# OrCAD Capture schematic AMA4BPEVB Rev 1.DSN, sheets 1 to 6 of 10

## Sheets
1 P03: Power Supplies: size Custom; title: AMA4BPEVB; rev: 1; note: AMSCH-0088
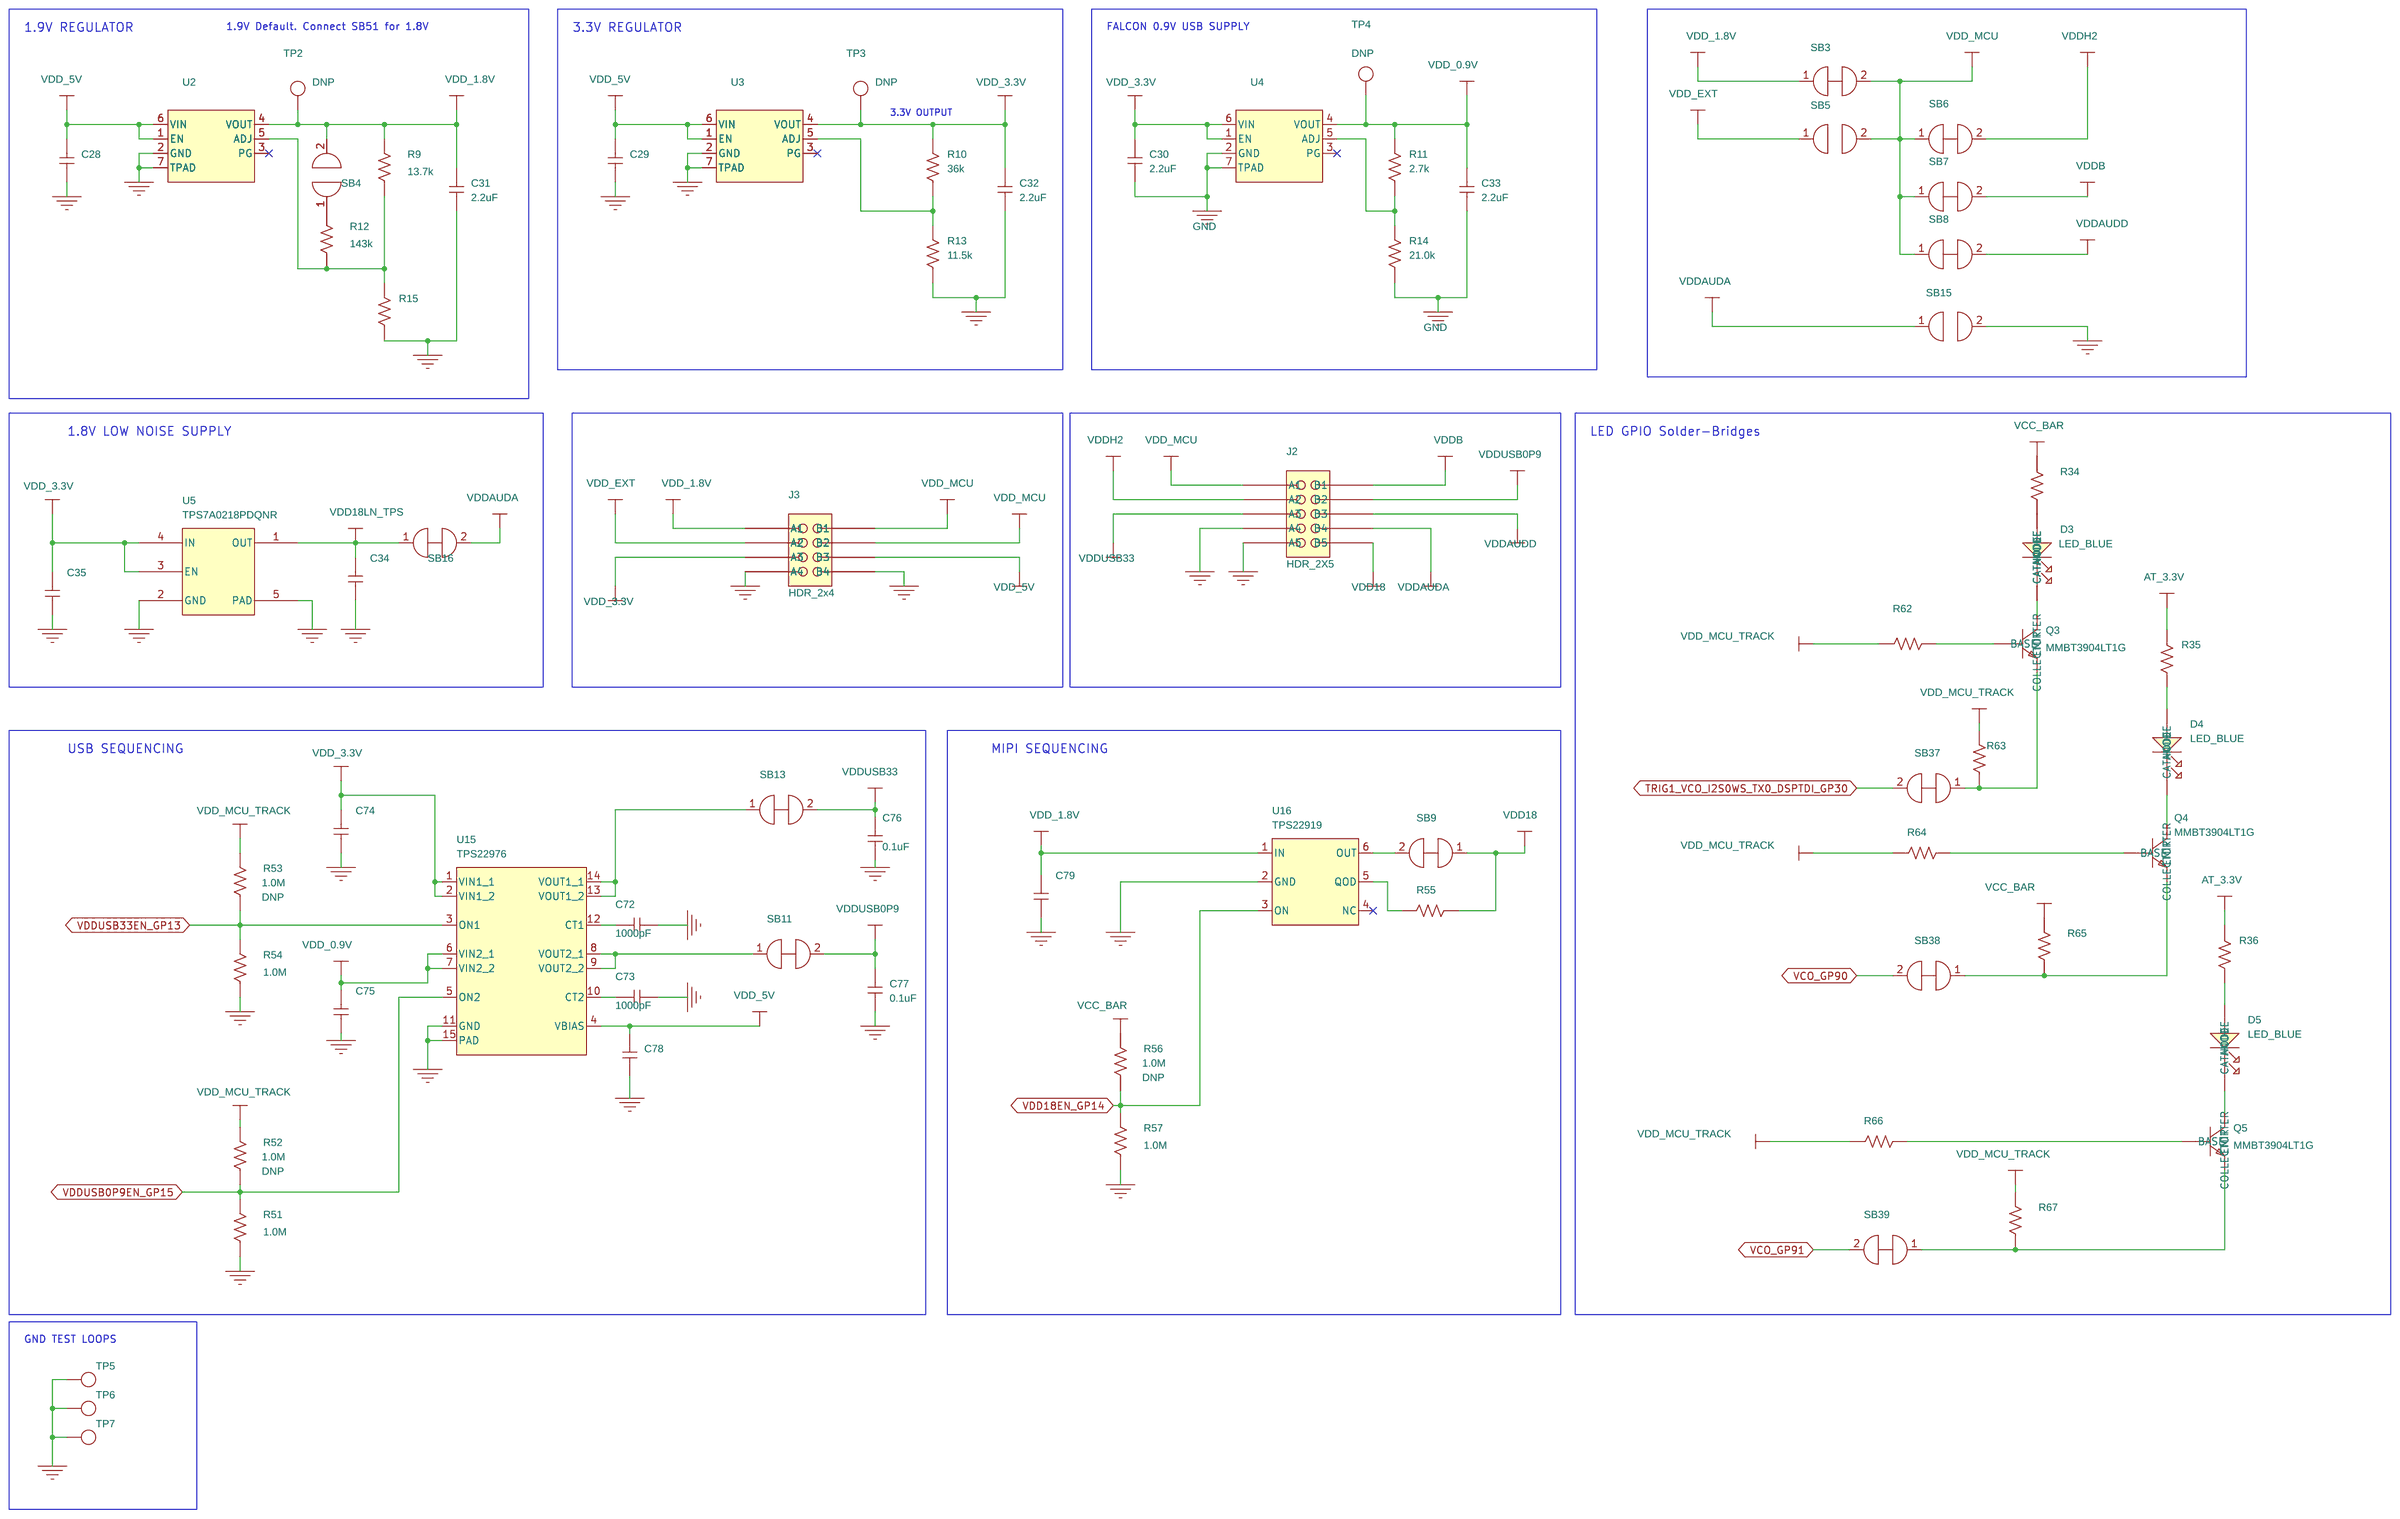
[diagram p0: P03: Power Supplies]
2 P05: Debugger: size Custom
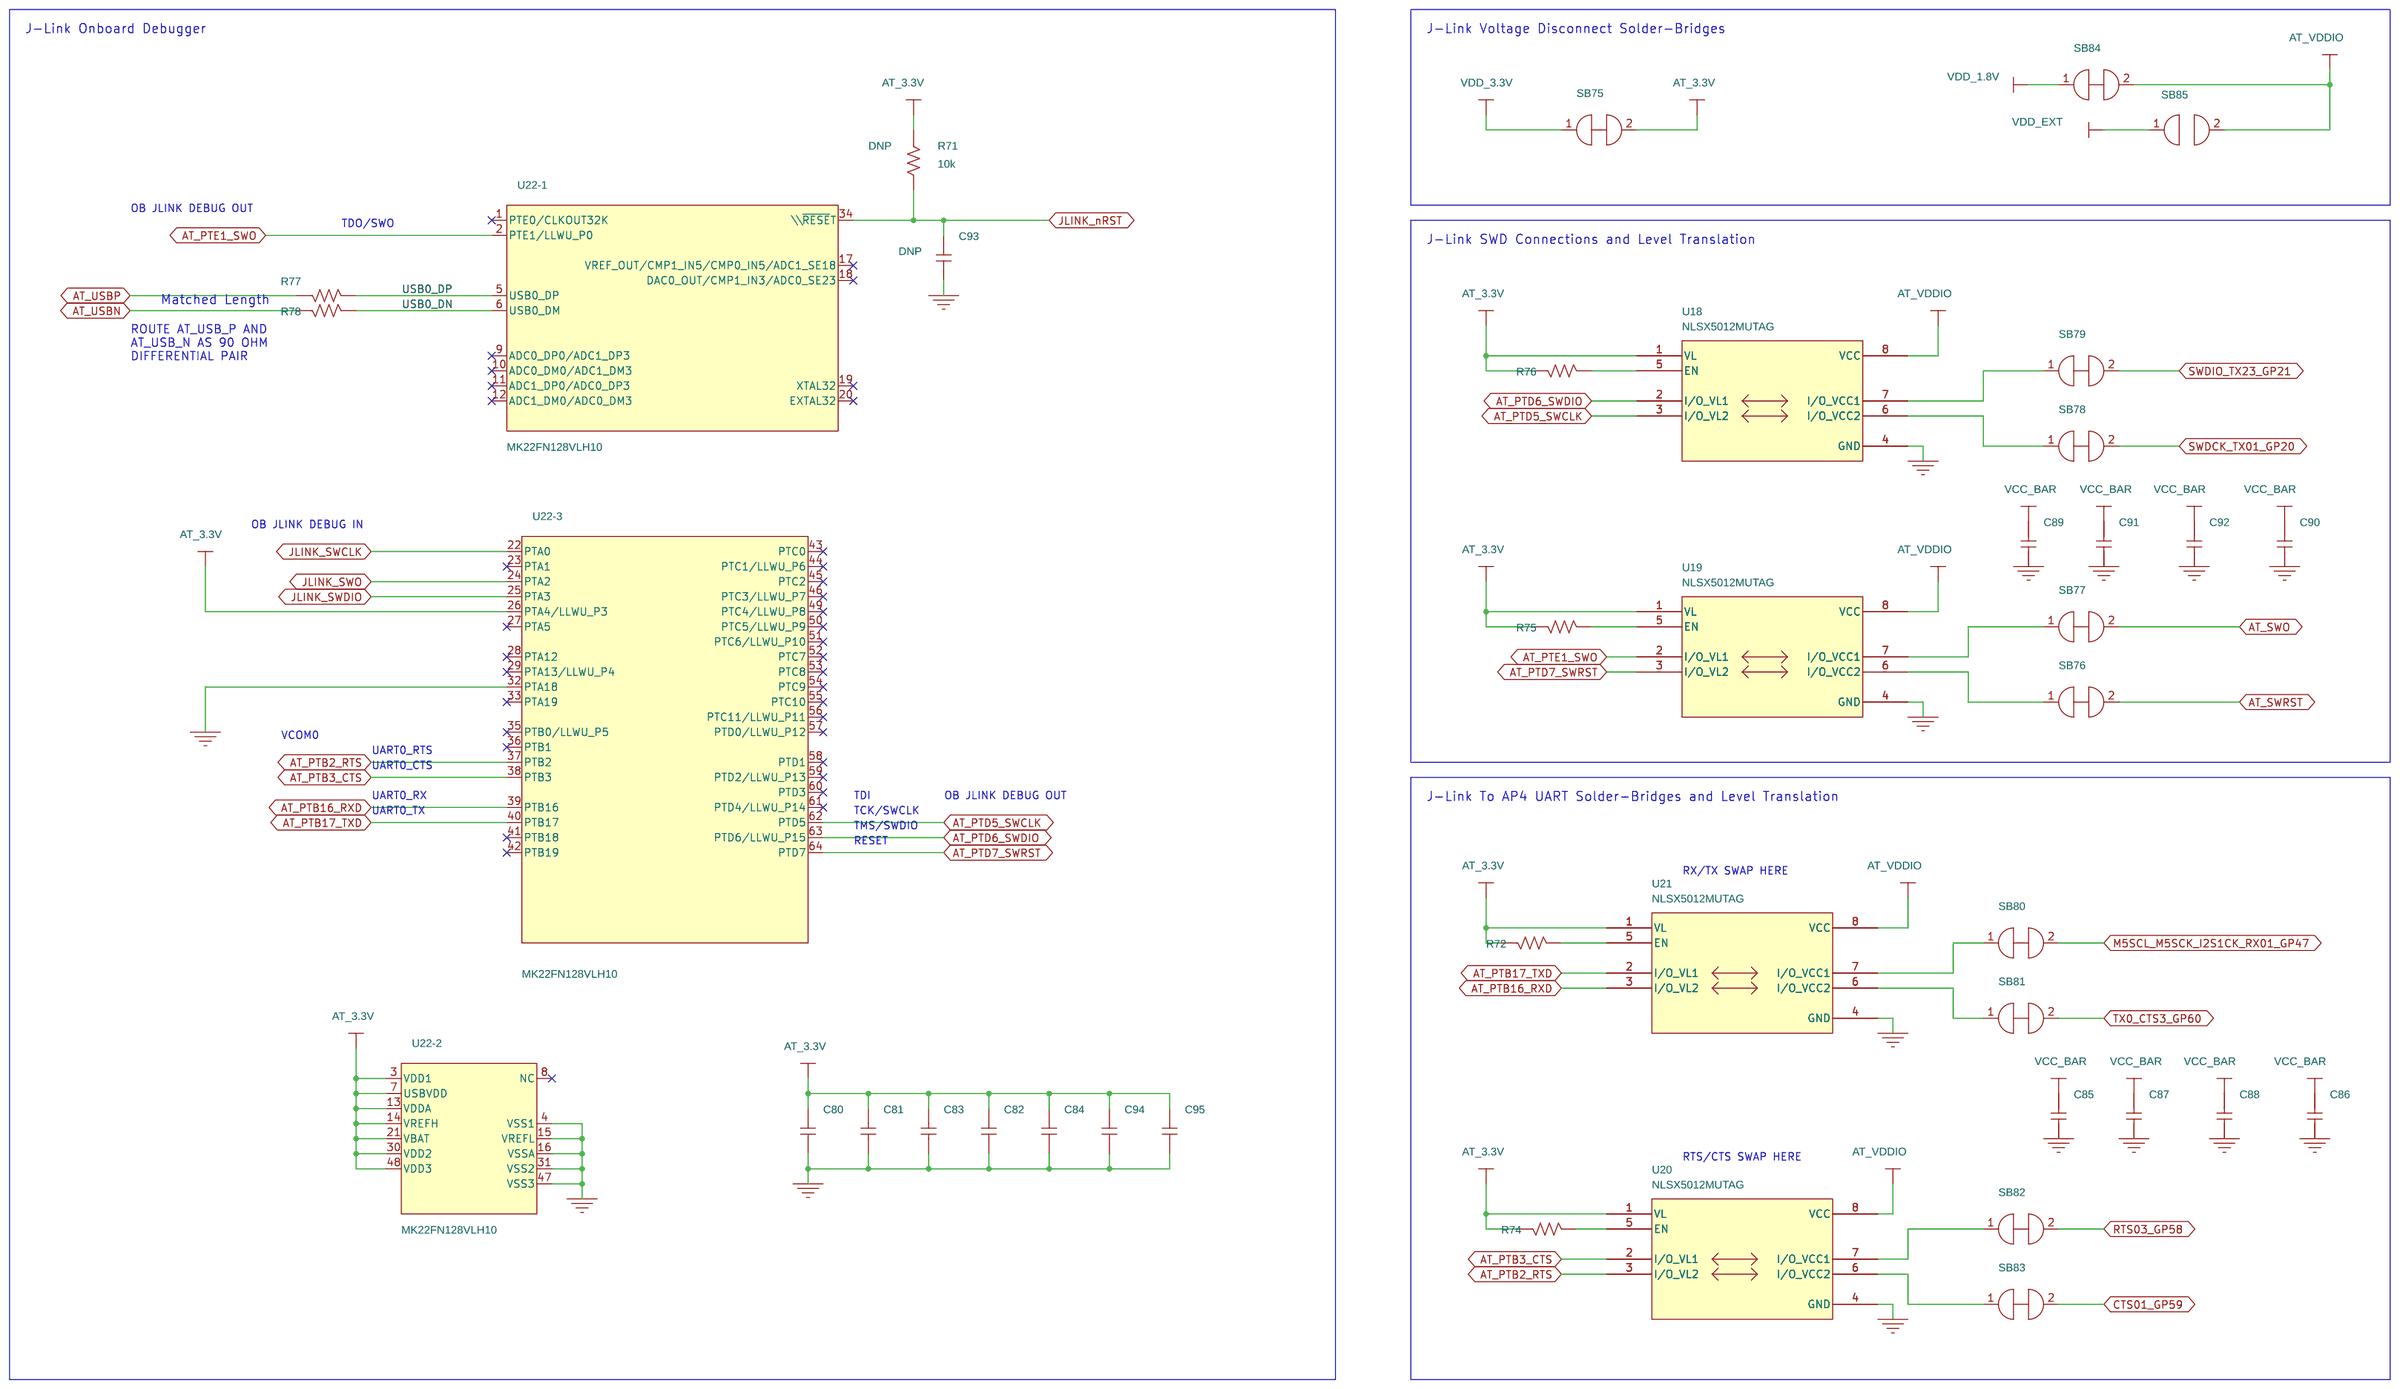
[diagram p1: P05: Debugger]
3 P04: USB: size Custom
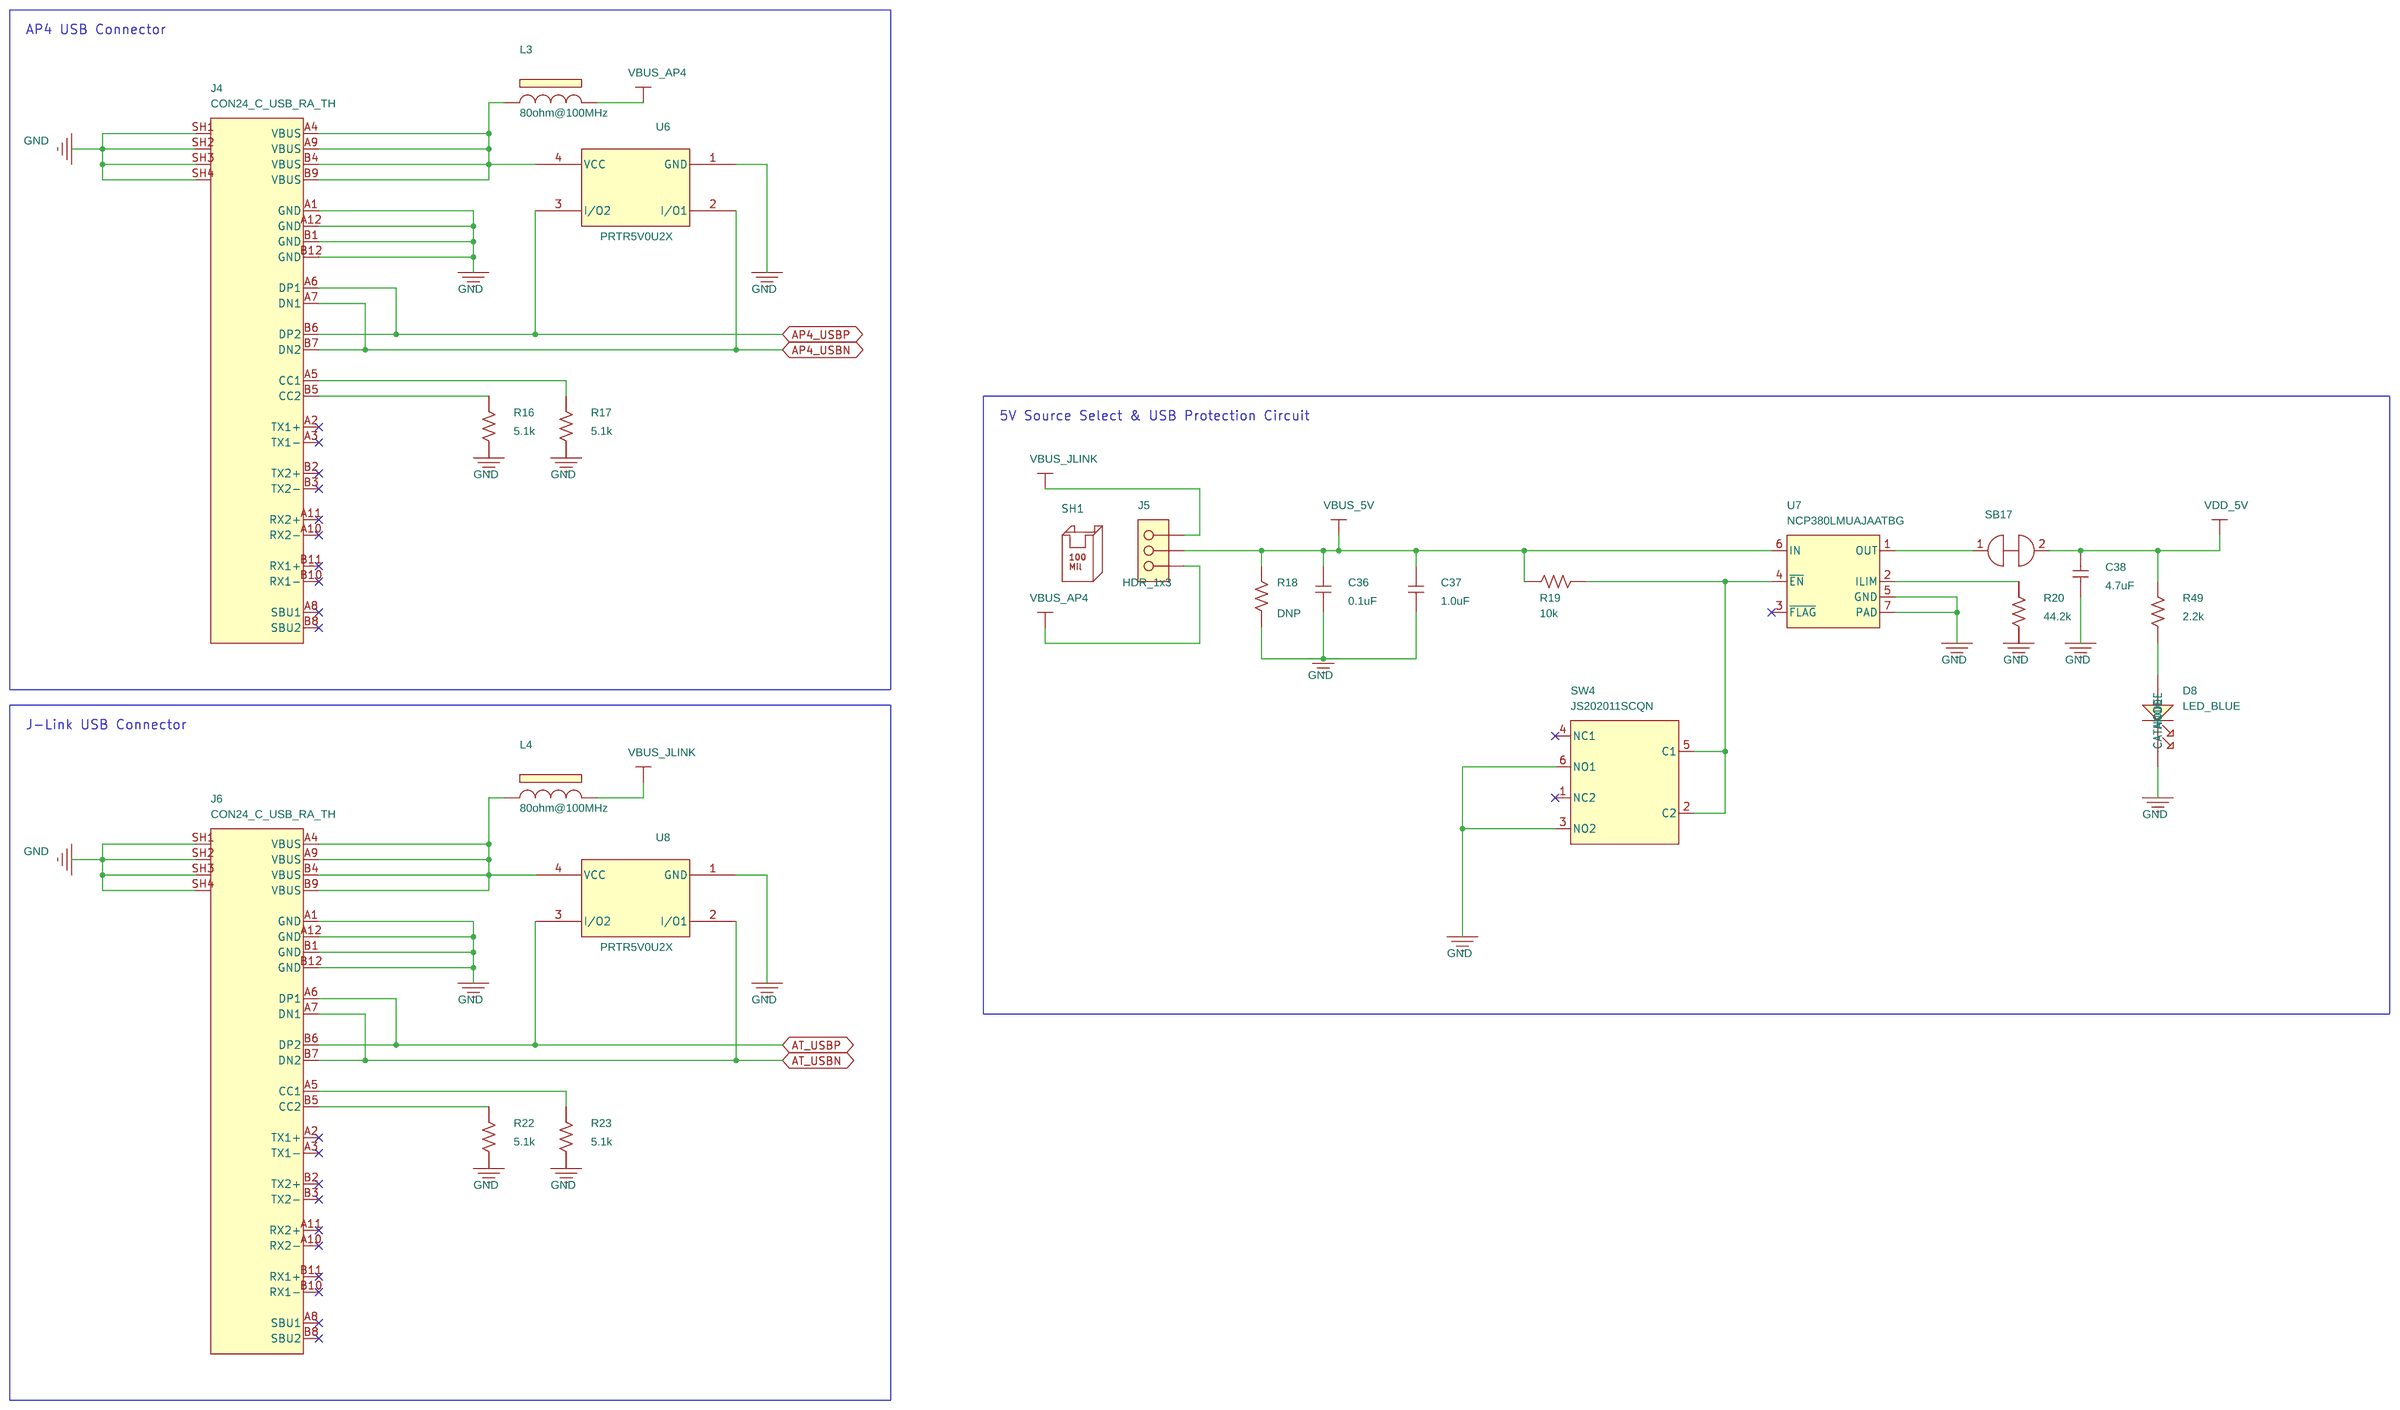
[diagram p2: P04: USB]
4 P06: GPIO Headers: size Custom
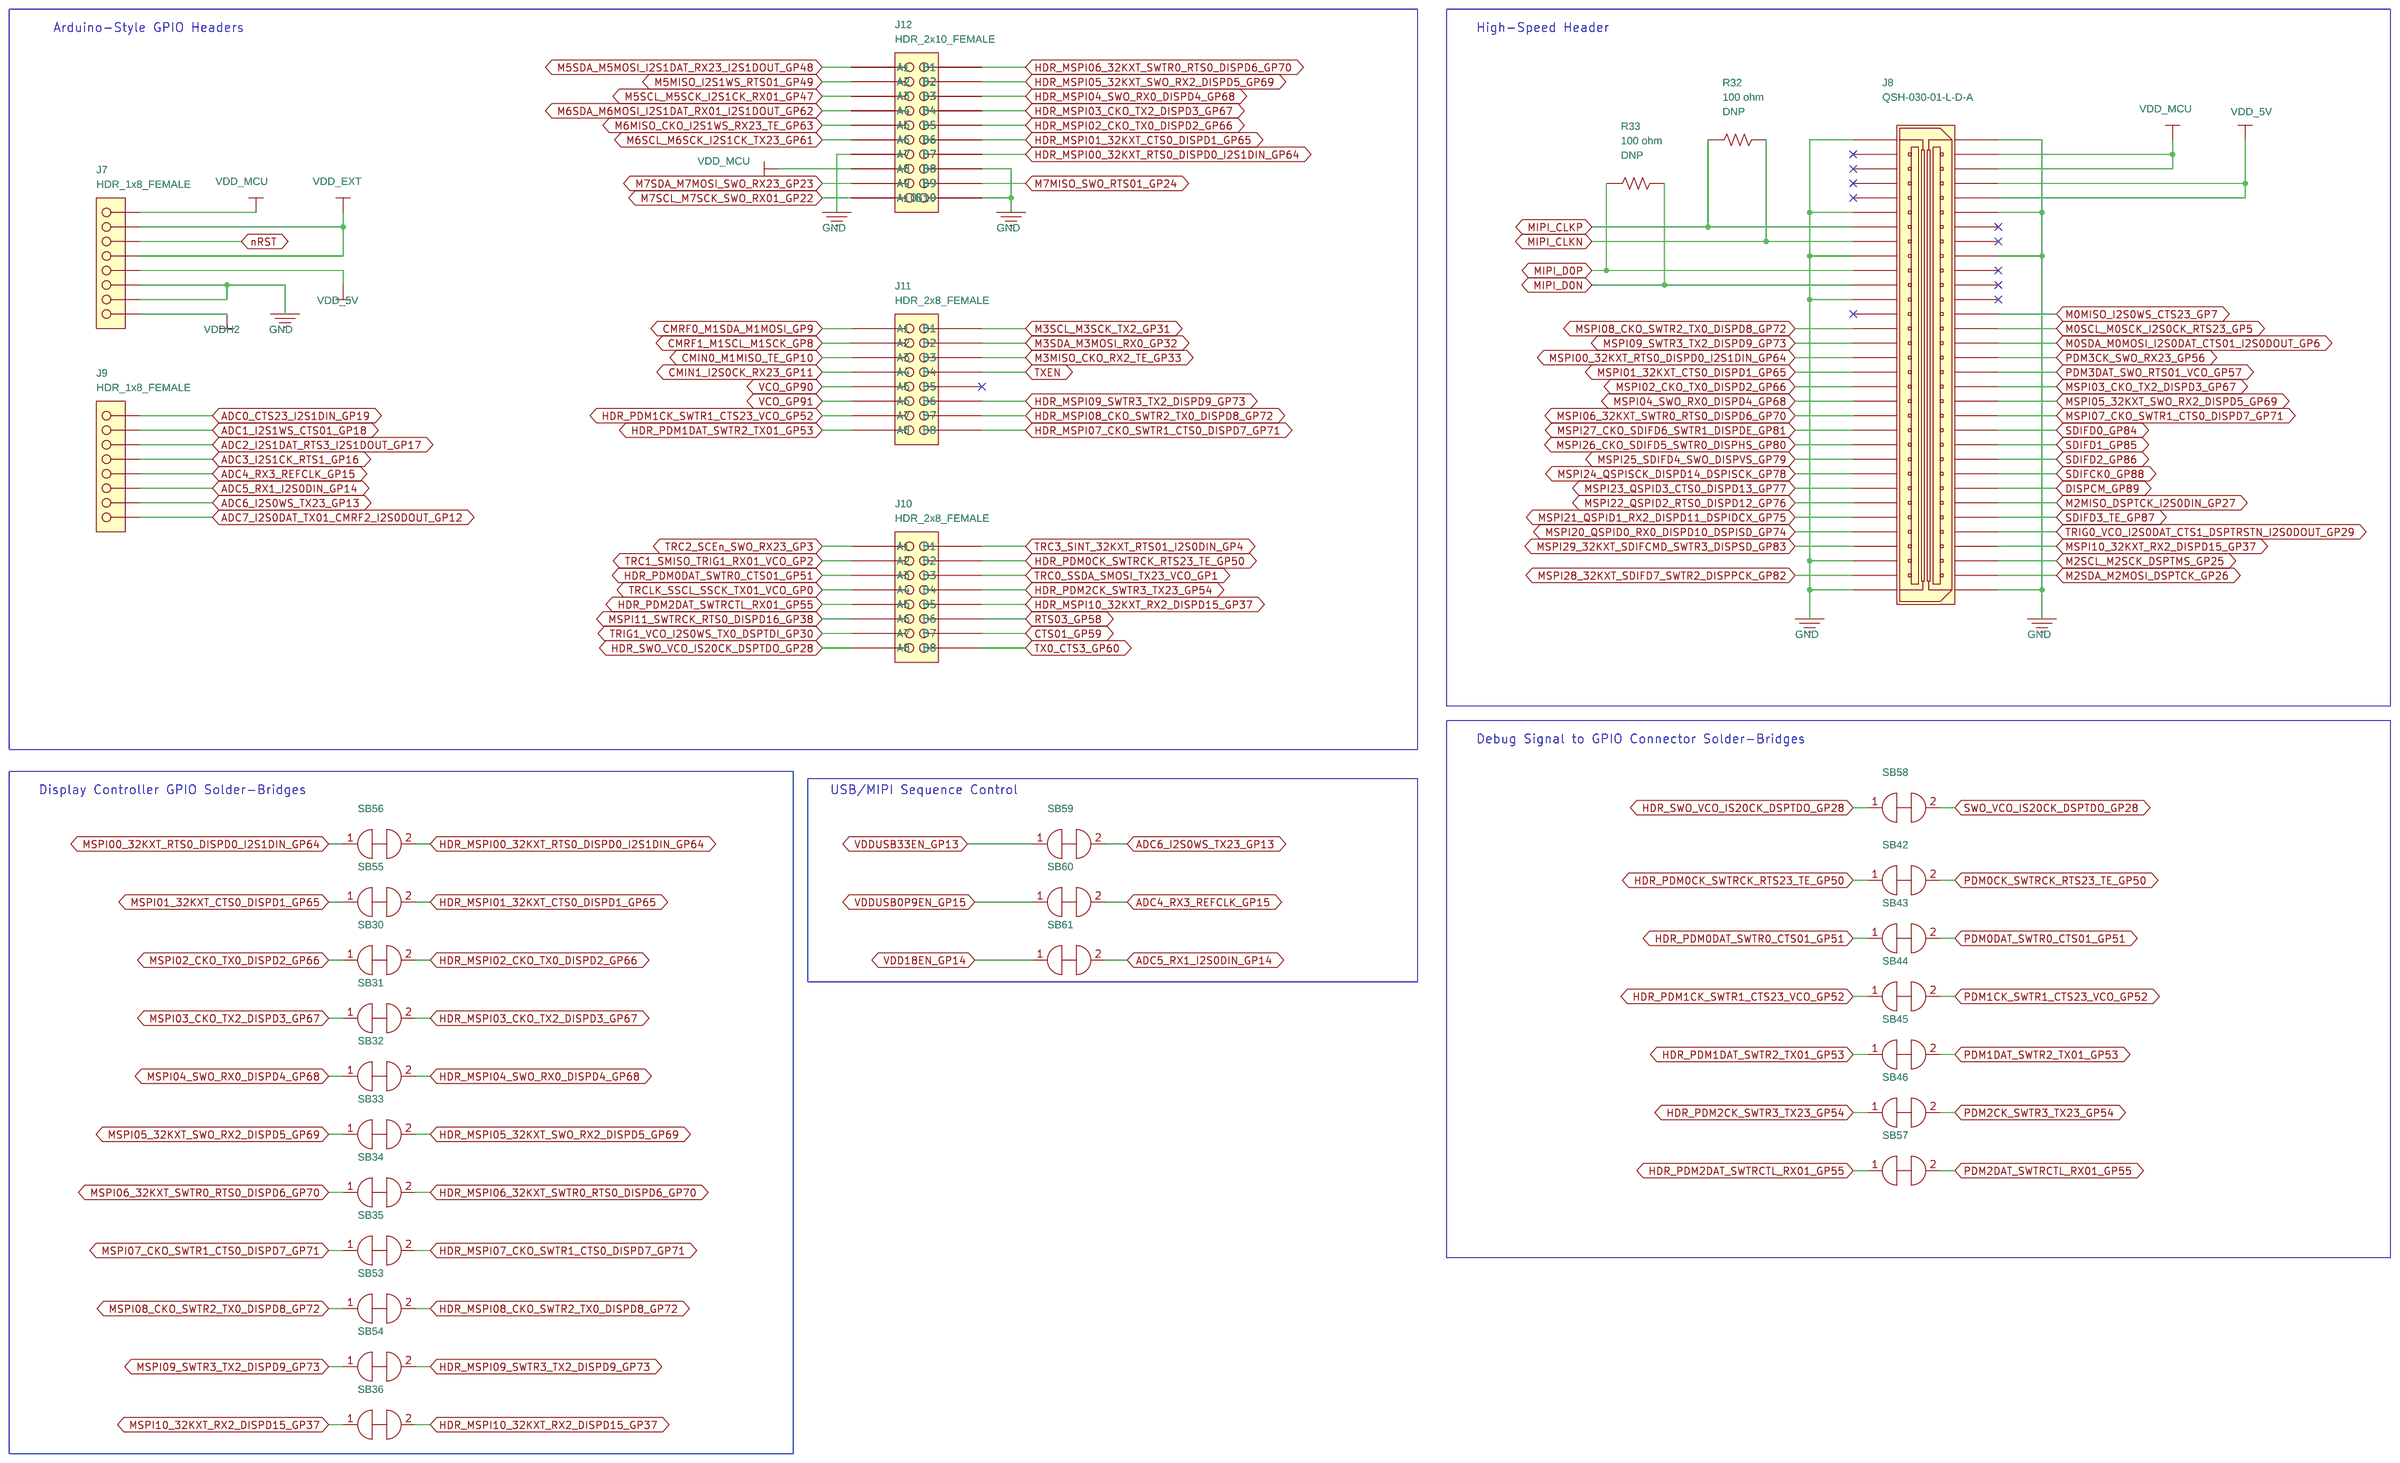
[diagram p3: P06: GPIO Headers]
5 P10: Testpoint Arrays: size Custom
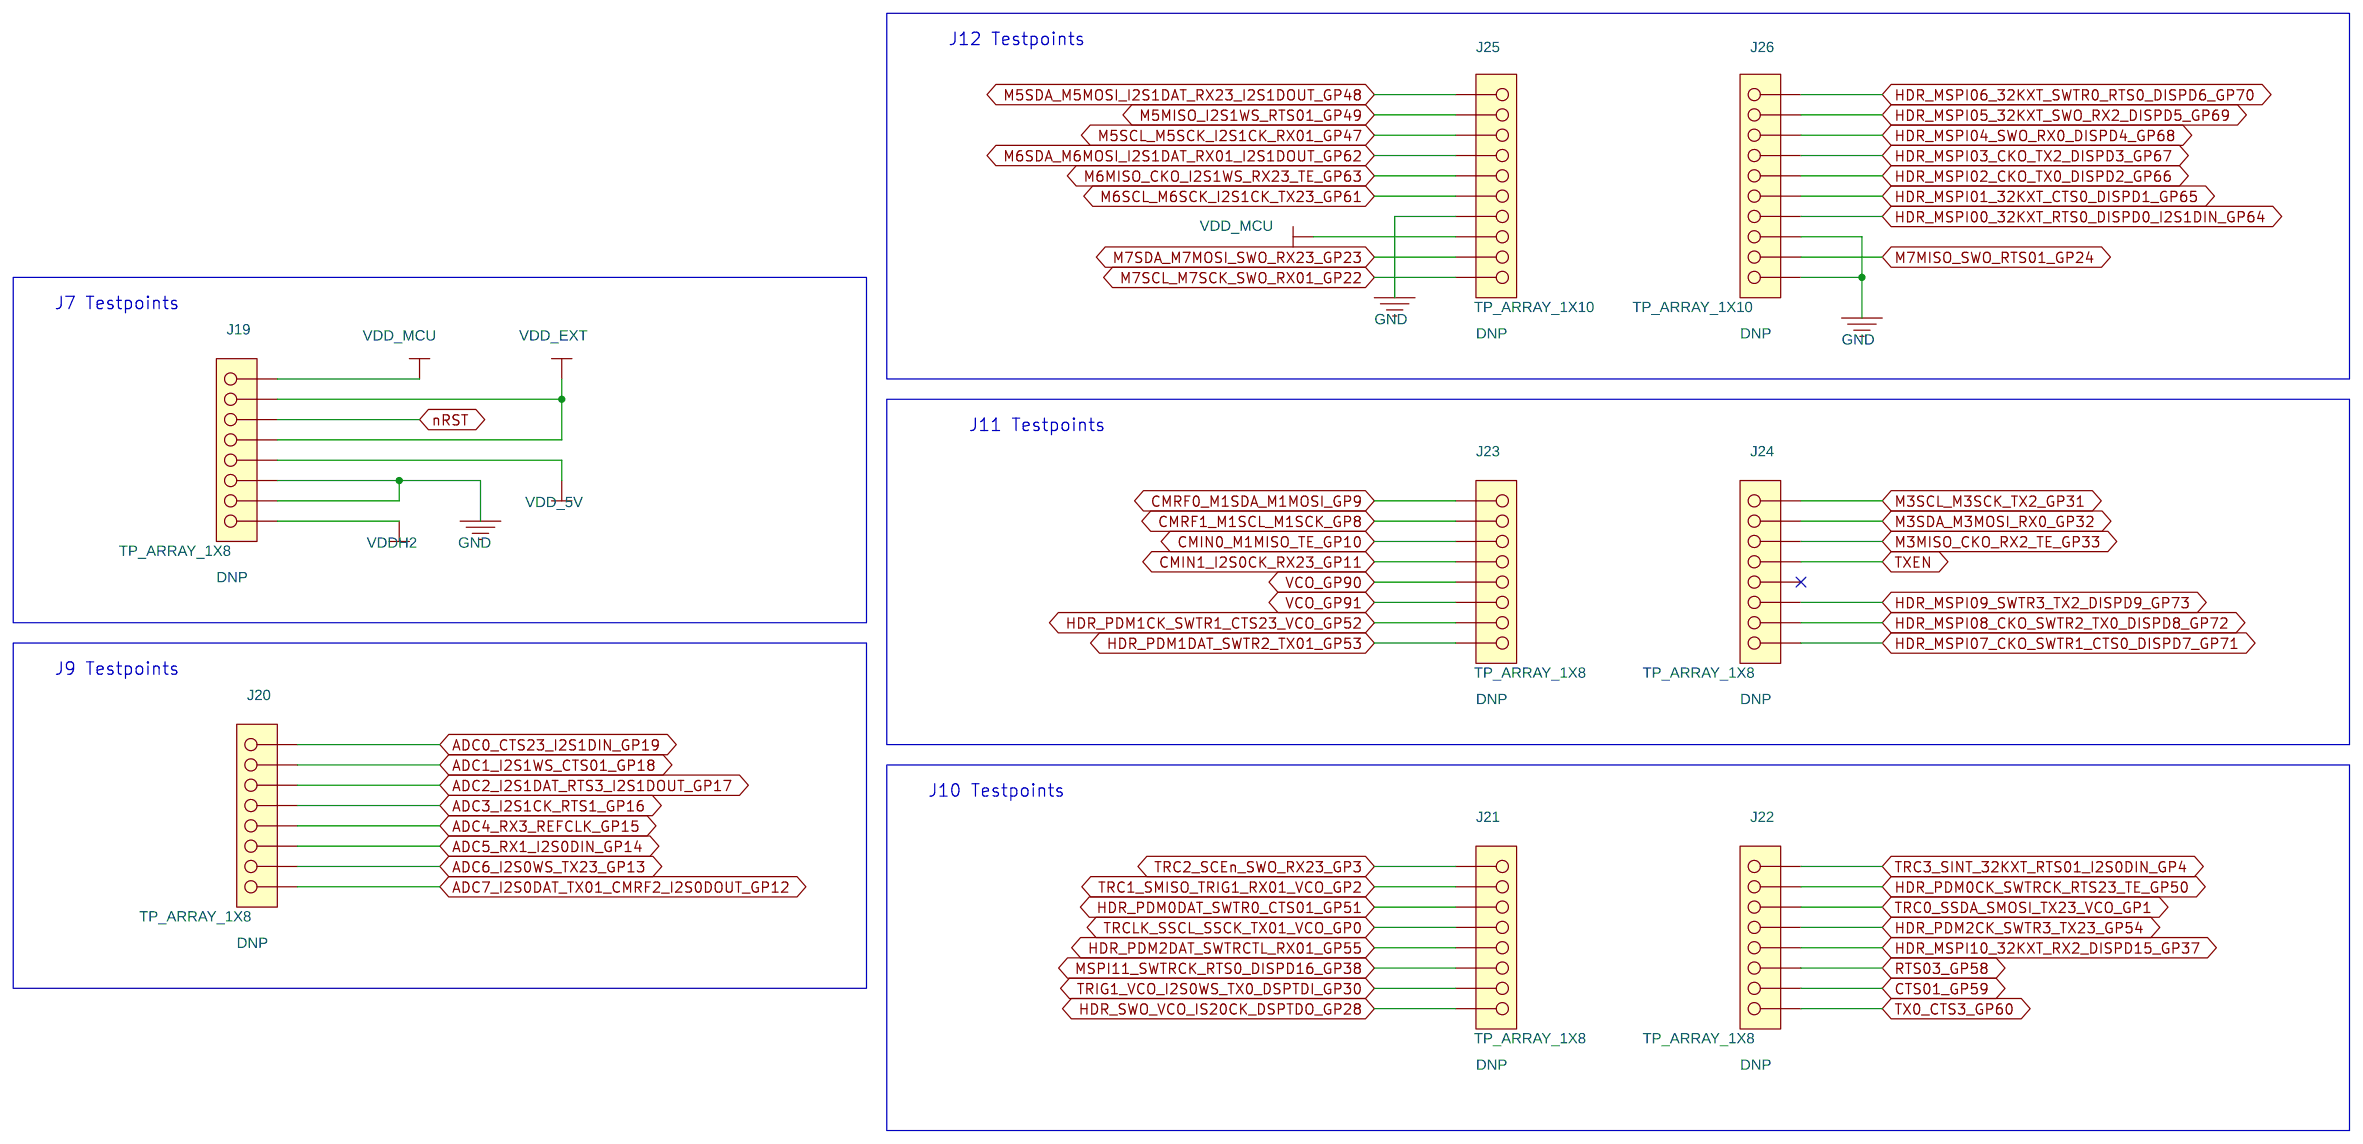
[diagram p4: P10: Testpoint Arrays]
6 P01: Revision History
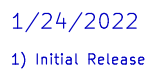
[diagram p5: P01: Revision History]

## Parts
sheet P03: Power Supplies
C28  1.0uF  [CC0402_25]
C29  1.0uF  [CC0402_25]
C30  2.2uF  [CC0402_25]
C31  2.2uF  [CC0402_25]
C32  2.2uF  [CC0402_25]
C33  2.2uF  [CC0402_25]
C34  1.0uF  [CC0201_HD]
C35  1.0uF  [CC0201_HD]
C72  1000pF  [CC0402_25]
C73  1000pF  [CC0402_25]
C74  1.0uF  [CC0201_HD]
C75  1.0uF  [CC0201_HD]
C76  0.1uF  [CC0201]
C77  0.1uF  [CC0201]
C78  1.0uF  [CC0402_25]
C79  1.0uF  [CC0201_HD]
D3  APA2107VBC/D  [2106_LED_RA]
D4  APA2107VBC/D  [2106_LED_RA]
D5  APA2107VBC/D  [2106_LED_RA]
J2  HDR_2X5  [HDR205_SM]
J3  HDR_2x4  [TSM-104-XX-XXX-DV]
Q3  MMBT3904LT1G  [SOT23]
Q4  MMBT3904LT1G  [SOT23]
Q5  MMBT3904LT1G  [SOT23]
R9  13.7k  [RC0402_25]
R10  36k  [RC0402_25]
R11  2.7k  [CC0201_HD]
R12  143k  [RC0402_25]
R13  11.5k  [RC0402_25]
R14  21.0k  [CC0201_HD]
R15  10.0k  [RC0402_25]
R34  10.0k  [RC0402_25]
R35  10.0k  [RC0402_25]
R36  10.0k  [RC0402_25]
R51  1.0M  [RC0402_25]
R52  1.0M  [RC0402_25]
R53  1.0M  [RC0402_25]
R54  1.0M  [RC0402_25]
R55  0 ohm  [CC0201_HD]
R56  1.0M  [RC0402_25]
R57  1.0M  [RC0402_25]
R62  10.0k  [RC0402_25]
R63  10.0k  [RC0402_25]
R64  10.0k  [RC0402_25]
R65  10.0k  [RC0402_25]
R66  10.0k  [RC0402_25]
R67  10.0k  [RC0402_25]
SB3  SB_SHORTED  [sb39x18_shorted]
SB4  SB_OPEN  [sb39x18]
SB5  SB_OPEN  [sb39x18]
SB6  SB_SHORTED  [sb39x18_shorted]
SB7  SB_SHORTED  [sb39x18_shorted]
SB8  SB_SHORTED  [sb39x18_shorted]
SB9  SB_SHORTED  [sb39x18_shorted]
SB11  SB_SHORTED  [sb39x18_shorted]
SB13  SB_SHORTED  [sb39x18_shorted]
SB15  SB_OPEN  [sb39x18]
SB16  SB_SHORTED  [sb39x18_shorted]
SB37  SB_SHORTED  [sb39x18_shorted]
SB38  SB_SHORTED  [sb39x18_shorted]
SB39  SB_SHORTED  [sb39x18_shorted]
TP2  TESTLOOP_LP  [test_loop]
TP3  TESTLOOP_LP  [test_loop]
TP4  TESTLOOP_LP  [test_loop]
TP5  TESTLOOP  [TEST_PIN_TP107]
TP6  TESTLOOP  [TEST_PIN_TP107]
TP7  TESTLOOP  [TEST_PIN_TP107]
U2  LD39100  [dfn6_0p95_3x3mm]
U3  LD39100  [dfn6_0p95_3x3mm]
U4  LD39100  [dfn6_0p95_3x3mm]
U5  TPS7A0218PDQNR  [x2son_1x1]
U15  TPS22976  [r_pwson_n14_3x2_update]
U16  TPS22919  [SC70-6]
sheet P04: USB
C36  0.1uF  [CC0402_25]
C37  1.0uF  [CC0402_25]
C38  4.7uF  [CC0402_25]
D8  APA2107VBC/D  [2106_LED_RA]
J4  CON24_C_USB_RA_TH  [CON24_C_USB_RA_TH]
J5  HDR_1x3  [HDR_1x3_100mil_SMD]
J6  CON24_C_USB_RA_TH  [CON24_C_USB_RA_TH]
L3  80ohm@100MHz  [1206_CC]
L4  80ohm@100MHz  [1206_CC]
R16  5.1k  [RC0402_25]
R17  5.1k  [RC0402_25]
R18  4.7k  [RC0402_25]
R19  10k  [RC0402_25]
R20  44.2k  [RC0402_25]
R22  5.1k  [RC0402_25]
R23  5.1k  [RC0402_25]
R49  2.2k  [RC0402_25]
SB17  SB_SHORTED  [sb39x18_shorted]
SH1  SNT-100-BL-G
SW4  JS202011SCQN  [sot23-6_JS]
U6  PRTR5V0U2X  [sot143-25x60]
U7  NCP380LMUAJAATBG  [udfn6_2x2]
U8  PRTR5V0U2X  [sot143-25x60]
sheet P05: Debugger
C80  0.1uF  [CC0201]
C81  0.1uF  [CC0201]
C82  0.1uF  [CC0201]
C83  0.1uF  [CC0201]
C84  0.1uF  [CC0201]
C85  0.1uF  [CC0201]
C86  0.1uF  [CC0201]
C87  0.1uF  [CC0201]
C88  0.1uF  [CC0201]
C89  0.1uF  [CC0201]
C90  0.1uF  [CC0201]
C91  0.1uF  [CC0201]
C92  0.1uF  [CC0201]
C93  0.1uF  [CC0201]
C94  0.1uF  [CC0201]
C95  0.1uF  [CC0201]
R71  10k  [RC0402_25]
R72  0 ohm  [CC0201_HD]
R74  0 ohm  [CC0201_HD]
R75  0 ohm  [CC0201_HD]
R76  0 ohm  [CC0201_HD]
R77  0 ohm  [CC0201_HD]
R78  0 ohm  [CC0201_HD]
SB75  SB_SHORTED  [sb39x18_shorted]
SB76  SB_SHORTED  [sb39x18_shorted]
SB77  SB_SHORTED  [sb39x18_shorted]
SB78  SB_SHORTED  [sb39x18_shorted]
SB79  SB_SHORTED  [sb39x18_shorted]
SB80  SB_SHORTED  [sb39x18_shorted]
SB81  SB_SHORTED  [sb39x18_shorted]
SB82  SB_SHORTED  [sb39x18_shorted]
SB83  SB_SHORTED  [sb39x18_shorted]
SB84  SB_SHORTED  [sb39x18_shorted]
SB85  SB_OPEN  [sb39x18]
U18  NLSX5012MUTAG  [udfn8_0p4_1p2x1p8]
U19  NLSX5012MUTAG  [udfn8_0p4_1p2x1p8]
U20  NLSX5012MUTAG  [udfn8_0p4_1p2x1p8]
U21  NLSX5012MUTAG  [udfn8_0p4_1p2x1p8]
U22  MK22FN128VLH10  [lqfp64_0p5_10x10]  (sections -1,-2,-3)
sheet P06: GPIO Headers
J7  HDR_1x8_FEMALE  [SSM-108-L-SV-P]
J8  QSH-030-01-L-D-A  [CON_60S_QSH_SM_A]
J9  HDR_1x8_FEMALE  [SSM-108-L-SV-P]
J10  HDR_2x8_FEMALE  [SSM-108-L-DV-P]
J11  HDR_2x8_FEMALE  [SSM-108-L-DV-P]
J12  HDR_2x10_FEMALE  [SSM-110-L-DV-P]
R32  100 ohm  [CC0201_HD]
R33  100 ohm  [CC0201_HD]
SB30  SB_SHORTED  [sb39x18_shorted]
SB31  SB_SHORTED  [sb39x18_shorted]
SB32  SB_SHORTED  [sb39x18_shorted]
SB33  SB_SHORTED  [sb39x18_shorted]
SB34  SB_SHORTED  [sb39x18_shorted]
SB35  SB_SHORTED  [sb39x18_shorted]
SB36  SB_SHORTED  [sb39x18_shorted]
SB42  SB_SHORTED  [sb39x18_shorted]
SB43  SB_SHORTED  [sb39x18_shorted]
SB44  SB_SHORTED  [sb39x18_shorted]
SB45  SB_SHORTED  [sb39x18_shorted]
SB46  SB_SHORTED  [sb39x18_shorted]
SB53  SB_SHORTED  [sb39x18_shorted]
SB54  SB_SHORTED  [sb39x18_shorted]
SB55  SB_SHORTED  [sb39x18_shorted]
SB56  SB_SHORTED  [sb39x18_shorted]
SB57  SB_SHORTED  [sb39x18_shorted]
SB58  SB_SHORTED  [sb39x18_shorted]
SB59  SB_SHORTED  [sb39x18_shorted]
SB60  SB_SHORTED  [sb39x18_shorted]
SB61  SB_SHORTED  [sb39x18_shorted]
sheet P10: Testpoint Arrays
J19  TP_ARRAY_1X8  [tp35h59p_1x8]
J20  TP_ARRAY_1X8  [tp35h59p_1x8]
J21  TP_ARRAY_1X8  [tp35h59p_1x8]
J22  TP_ARRAY_1X8  [tp35h59p_1x8]
J23  TP_ARRAY_1X8  [tp35h59p_1x8]
J24  TP_ARRAY_1X8  [tp35h59p_1x8]
J25  TP_ARRAY_1X10  [tp35h59p_1x10]
J26  TP_ARRAY_1X10  [tp35h59p_1x10]

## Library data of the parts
C28 C29 C78 = CAP_NP: CAP CER 1uF 25V 20% X5R 0402; AMBIQ_PN: AM-02-1115; DISTRIBUTOR: MOUSER; DISTRIBUTOR_PN: 963-TMK105BJ105MV-F; Dielectric Material: X5R; HEIGHT: 0.55MM; LEAD_FREE: Yes; MFG_NAME: TAIYO YUDEN; MFG_PN: TMK105BJ105MV-F / TMK105BJ105MV-F; Manufacturer_Datasheet: http://ds.yuden.co.jp/TYCOMPAS/ut/detail.do?productNo=TMK105BJ105MV-F&fileName=TMK105BJ105MV-F_SS&mode=specSheetDownload; PART_TYPE: CER\0402; PCB_FOOTPRINT_OPTIONS: CC0402_25,CC0402_HD,CC0402_CC; PEAK_REFLOW_TEMP: 260; Package Size: 0402; Package Type: SMD; ROHS: Yes; STATUS: Production; TOL: 20%; Temp Coefficient (ppm/Deg C): X5R; VOLTAGE: 10V
C30-C33 = CAP_NP: CAP CER 2.2UF 16V 10% X5R 0402; AMBIQ_PN: AM-02-1103; DISTRIBUTOR: MOUSER; DISTRIBUTOR_PN: 81-GRM155R61C225KE1D; Dielectric Material: X5R; HEIGHT: 0.52MM; LEAD_FREE: Yes; MFG_NAME: MURATA; MFG_PN: GRM155R61C225KE11D; Manufacturer_Datasheet: http://psearch.en.murata.com/capacitor/product/GRM155R61C225KE11%23.html; PART_TYPE: CER\0402; Package Size: 0402; Package Type: SMD; ROHS: Yes; STATUS: Production; TOL: 10%; VOLTAGE: 16V
C34 C35 C74 C75 C79 = CAP_NP: CAP CER 1.0UF 10V 20% X6S 0201; AMBIQ_PN: AM-02-1091; BIAS_25%: 0.60uF; BIAS_50%: 0.39uF; BIAS_75%: 0.25uF; DISTRIBUTOR: MOUSER; DISTRIBUTOR_PN: 81-GRM033C81A105ME5D; Dielectric Material: X6S; FPLIST: CC0201,CC0201_HD,CC0201_3PIN,CC0201_CC; HEIGHT: 0.33MM; LEAD_FREE: Yes; MFG_NAME: MURATA; MFG_PN: GRM033C81A105ME05D; Manufacturer_Datasheet: http://psearch.en.murata.com/capacitor/product/GRM033C81A105ME05%23.pdf; PART_TYPE: CER\0201; PCB_FOOTPRINT_OPTIONS: CC0201,CC0201_HD,CC0201_3PIN,CC0201_CC; PEAK_REFLOW_TEMP: 260; Package Size: 0201; Package Type: SMD; ROHS: Yes; STATUS: Production; TOL: 20%; Temp Coefficient (ppm/Deg C): X6S; VOLTAGE: 10V
C72 C73 = CAP_NP: CAP CER 1000PF 25V 10% X7R 0402; AMBIQ_PN: AM-02-0294; Dielectric Material: CERAMIC; HEIGHT: 0.635MM; LEAD_FREE: Yes; MFG_NAME: VENKEL COMPANY; MFG_PN: C0402X7R250-102KNE; Manufacturer_Datasheet: http://www.venkel.com/FinalPDFs/PID_C.pdf; PART_TYPE: CER\0402; Package Size: 0402; Package Type: embossed tape; ROHS: Yes; STATUS: Production; TOL: 10%
C76 C77 = CAP_NP: CAP CER 0.1UF 10V 10% X5R 0201; AMBIQ_PN: AM-02-1050; DISTRIBUTOR: DIGIKEY; DISTRIBUTOR_PN: 587-2241-1-ND; Dielectric Material: X5R; FPLIST: CC0201,CC0201_HD,CC0201_3PIN,CC0201_CC; HEIGHT: 0.33MM; LEAD_FREE: Yes; MFG_NAME: TAIYO YUDEN; MFG_PN: LMK063BJ104KP-F; Manufacturer_Datasheet: http://www.yuden.co.jp/or/product/category/capacitor/LMK063BJ104KP-F.pdf; PART_TYPE: CER\0201; Package Size: 0201; Package Type: SMD; ROHS: Yes; STATUS: Production; TOL: 10%; VOLTAGE: 10V
D3-D5 D8 = LED: LED BLUE CLEAR 3.3V 20mA 2106 SMD R/A; AMBIQ_PN: AM-05-0504; DISTRIBUTOR: DIGIKEY; DISTRIBUTOR_PN: 754-2102-1-ND; HEIGHT: 0.6MM; LEAD_FREE: Yes; MFG_NAME: KINGBRIGHT; Manufacturer_Datasheet: http://www.kingbrightusa.com/images/catalog/SPEC/APA2107VBC-D.pdf; NOTES: LED_BLUE; PART_TYPE: LED\BLUE; ROHS: Yes; Rated Current: 20mA; Rated Voltage: 3.3V; STATUS: Production
J2 = CONN_HDR_5X2: HDR 2X5 SMT 100MIL CTR 380H AU; AMBIQ_PN: AM-03-0743; HEIGHT: 9.65 MM; LEAD_FREE: Yes; MFG_NAME: SAMTEC; MFG_PN: TSM-105-01-S-DV-P-TR; Manufacturer_Datasheet: http://www.samtec.com/ftppub/pdf/TSM.PDF; PART_TYPE: HEADER; ROHS: Yes; STATUS: Production
J3 = CONN_HDR_4X2: HDR 2x4 SMD 100MIL PITCH 230MIL LEAD LENGTH; AMBIQ_PN: AM-03-1300; DISTRIBUTOR: DIGIKEY; DISTRIBUTOR_PN: SAM13288CT-ND; HEIGHT: 9.65MM; LEAD_FREE: Yes; MFG_NAME: SAMTEC; MFG_PN: TSM-104-01-S-DV-P; Manufacturer_Datasheet: https://www.mouser.com/datasheet/2/527/tsm-1370482.pdf; PART_TYPE: HEADER; Package Type: SMD; ROHS: Yes; STATUS: Production
Q3-Q5 = NPN: TRAN NPN GEN 200MA 40V SOT-23; AMBIQ_PN: AM-05-0319; HEIGHT: 1.11 MM; LEAD_FREE: Yes; MFG_NAME: ON SEMICONDUCTOR; Manufacturer_Datasheet: http://www.onsemi.com/pub/Collateral/MMBT3904LT1-D.PDF; PART_TYPE: TRANSISTOR\BJT; ROHS: Yes; Rated Current: 200MA; Rated Voltage: 40V; STATUS: Production
R9 = RES: RES MF 13.7K  1/16W 1% 0402; AMBIQ_PN: AM-01-0622; HEIGHT: 0.40 MM; LEAD_FREE: Yes; MFG_NAME: KOA SPEER; MFG_PN: RK73H1ETTP1372F; Manufacturer_Datasheet: http://www.koaspeer.com/pdfs/res5.pdf; PART_TYPE: 0402; Power Rating (Max) (W): 0.1W; ROHS: Yes; STATUS: Production; TOL: 1%
R10 = RES: RES MF 36K  1/16W 1% 0402; AMBIQ_PN: AM-01-1687; HEIGHT: 0.40 MM; LEAD_FREE: Yes; MFG_NAME: KOA SPEER; MFG_PN: RK73H1ETTP3602F; Manufacturer_Datasheet: http://www.koaspeer.com/pdfs/res5.pdf; PART_TYPE: 0402; PCB_FOOTPRINT_OPTIONS: RC0402_25,RC0402_HD,RC0402_CC; PEAK_REFLOW_TEMP: 260; Power Rating (Max) (W): 0.1W; ROHS: Yes; STATUS: Production; TOL: 1%
R11 = RES: RES TF 2.7k 1/20W 1% 0201; AMBIQ_PN: AM-01-2947; DISTRIBUTOR: MOUSER; DISTRIBUTOR_PN: 660-RK73H1HTTC2701F; HEIGHT: 0.26 MM; LEAD_FREE: Yes; MFG_NAME: KOA SPEER; MFG_PN: RK73H1HTTC2701F; Manufacturer_Datasheet: http://www.koaspeer.com/catimages/Products/RK73H/RK73H.pdf; PART_TYPE: 0201; Power Rating (Max) (W): 1/20W; ROHS: Yes; STATUS: Production; TOL: 1%; Type: SMD
R12 = RES: RES MF 143K  1/16W 1% 0402; AMBIQ_PN: AM-01-0663; HEIGHT: 0.40 MM; LEAD_FREE: Yes; MFG_NAME: KOA SPEER; MFG_PN: RK73H1ETTP1433F; Manufacturer_Datasheet: http://www.koaspeer.com/pdfs/res5.pdf; PART_TYPE: 0402; Power Rating (Max) (W): 0.1W; ROHS: Yes; STATUS: Production; TOL: 1%
R13 = RES: RES MF 11.5K  1/16W 1% 0402; AMBIQ_PN: AM-01-0513; HEIGHT: 0.40 MM; LEAD_FREE: Yes; MFG_NAME: KOA SPEER; MFG_PN: RK73H1ETTP1152F; Manufacturer_Datasheet: http://www.koaspeer.com/pdfs/res5.pdf; PART_TYPE: 0402; PCB_FOOTPRINT_OPTIONS: RC0402_25,RC0402_HD,RC0402_CC; PEAK_REFLOW_TEMP: 260; Power Rating (Max) (W): 0.1W; ROHS: Yes; STATUS: Production; TOL: 1%
R14 = RES: RES TF 21.0k 1/20W 1% 0201; AMBIQ_PN: AM-01-2945; DISTRIBUTOR: MOUSER; DISTRIBUTOR_PN: 71-CRCW020121K0FNED; HEIGHT: 0.26 MM; LEAD_FREE: Yes; MFG_NAME: VISHAY DALE; MFG_PN: CRCW020121K0FNED; Manufacturer_Datasheet: http://www.vishay.com/docs/20052/crcw0201e3.pdf; PART_TYPE: 0201; Power Rating (Max) (W): 1/20W; ROHS: Yes; STATUS: Production; TOL: 1%; Type: SMD
R15 R34-R36 R62-R67 = RES: RES TF 10.0K 1/16W 1% 0402; AMBIQ_PN: AM-01-2777; DISTRIBUTOR: DIGIKEY; DISTRIBUTOR_PN: 311-10.0KLRCT-ND; HEIGHT: 0.40 MM; LEAD_FREE: Yes; MFG_NAME: YAGEO; MFG_PN: RC0402FR-0710KL; Manufacturer_Datasheet: http://www.yageo.com/documents/recent/PYu-RC0402_51_RoHS_L_6.pdf; Material (Resistor): TF; NUM_RESISTORS: 1; PART_TYPE: 0402; PCB_FOOTPRINT_OPTIONS: RC0402_25,RC0402_HD,RC0402_CC; PEAK_REFLOW_TEMP: 260; Power Rating (Max) (W): 0.063W; ROHS: Yes; STATUS: Production; TOL: 1%; Type: SMD
R51 R54 R57 = RES: RES TF 1.0M 1/16W 5% RC0402; AMBIQ_PN: AM-01-0128; HEIGHT: 0.4 MM; LEAD_FREE: No; MFG_NAME: BOURNS; MFG_PN: CR0402JW105G; Manufacturer_Datasheet: http://www.bourns.com/pdfs/CR0402.pdf; PART_TYPE: 0402; Power Rating (Max) (W): 1/16W; ROHS: No; STATUS: Production; TOL: 5%; Type: SMD
R52 R53 R56 = RES: RES TF 1.0M 1/16W 5% RC0402; AMBIQ_PN: AM-01-0128; ASSY_OPT: DNP; HEIGHT: 0.4 MM; LEAD_FREE: No; MFG_NAME: BOURNS; MFG_PN: CR0402JW105G; Manufacturer_Datasheet: http://www.bourns.com/pdfs/CR0402.pdf; PART_TYPE: 0402; Power Rating (Max) (W): 1/16W; ROHS: No; STATUS: Production; TOL: 5%; Type: SMD
R55 R72 R74-R78 = RES: RES TF ZERO OHM 1/20W 1% 0201; AMBIQ_PN: AM-01-0014; DISTRIBUTOR: DIGIKEY; DISTRIBUTOR_PN: P0.0AGDKR-ND; HEIGHT: 0.30 MM; LEAD_FREE: Yes; MFG_NAME: PANASONIC; MFG_PN: ERJ-1GE0R00C; Manufacturer_Datasheet: http://industrial.panasonic.com/www-data/pdf/AOA0000/AOA0000CE2.pdf; NUM_RESISTORS: 1; PART_TYPE: 0201; PCB_FOOTPRINT_OPTIONS: RC0201,RC0201_X2,RC0201_CC; PEAK_REFLOW_TEMP: 260; Power Rating (Max) (W): 1/20W; ROHS: Yes; STATUS: Production; TOL: 1%; Type: SMD
SB3 SB6-SB8 SB16 SB17 SB30-SB36 SB42-SB46 SB53-SB61 = SB_Shorted: Solder-Bridge, Shorted, 39X18 PAD; AMBIQ_PN: AM-03-1291; ASSY_OPT: DNP; PART_TYPE: MISC; ROHS: Yes; STATUS: Production
SB4 SB5 SB15 = SB_Open: Solder-Bridge, No Connect, 39X18 PAD; AMBIQ_PN: AM-03-1290; ASSY_OPT: DNP; PART_TYPE: MISC; ROHS: Yes; STATUS: Production
SB9 SB11 SB13 SB37-SB39 SB75-SB84 = SB_Shorted: Solder-Bridge, Shorted, 39X18 PAD; AMBIQ_PN: AM-03-1291; PART_TYPE: MISC; ROHS: Yes; STATUS: Production
TP2-TP4 = TestLoop: TEST POINT PC LOW PRO W/OUT BASE; AMBIQ_PN: AM-03-1228; ASSY_OPT: DNP; DISTRIBUTOR: DIGIKEY; DISTRIBUTOR_PN: 5021KCT-ND; HEIGHT: 2.54MM; LEAD_FREE: Yes; MFG_NAME: KEYSTONE ELECTRONICS; MFG_PN: 5021; Manufacturer_Datasheet: http://www.keyelco.com/product-pdf.cfm?p=1325; Number Of Connectors: 1; Number Of Contact Rows: 1; Number Of Contacts: 1; PART_TYPE: TEST_POINT; ROHS: Yes; STATUS: Production; Type: TEST_POINT
TP5-TP7 = TestLoop: TEST POINT PAD SIZE 4.7MM X 3.5MM SN; AMBIQ_PN: AM-03-1220; DISTRIBUTOR: DIGIKEY; DISTRIBUTOR_PN: 5016KCT-ND; HEIGHT: 2.29MM; LEAD_FREE: Yes; MFG_NAME: KEYSTONE ELECTRONICS; MFG_PN: 5016; Manufacturer_Datasheet: http://www.keyelco.com/product-pdf.cfm?p=1354; Number Of Connectors: 1; Number Of Contact Rows: 1; Number Of Contacts: 1; PART_TYPE: TEST_POINT; Package Size: 4.7MM X 3.5MM; ROHS: Yes; STATUS: Production; Type: TEST_POINT
U2-U4 = LD39100: IC VREG ADJ 1.5V-5.5V 1.0A 6DFN; # Pins: 6; AMBIQ_PN: AM-07-2218; DISTRIBUTOR: DIGIKEY; DISTRIBUTOR_PN: 497-11013-1-ND; HEIGHT: 1.00MM; IC Type: LDO REGULATOR; LEAD_FREE: Yes; MFG_NAME: ST MICROELECTRONICS; MFG_PN: LD39100PUR; Manufacturer_Datasheet: http://www.st.com/web/en/resource/technical/document/datasheet/CD00233788.pdf; PART_TYPE: VOLTAGE\REGULATOR; PEAK_REFLOW_TEMP: 260; ROHS: Yes; STATUS: Production
U5 = TPS7A0218PDQNR: IC VREG LDO 1.8V 200MA 1.5V TO 6V X2SON; AMBIQ_PN: AM-07-2340; DISTRIBUTOR: MOUSER; DISTRIBUTOR_PN: 595-TPS7A0218PDQNR; HEIGHT: 0.4MM; IC Type: Voltage Regulator 1.8V; LEAD_FREE: Yes; MFG_NAME: TEXAS INSTRUMENTS; Manufacturer_Datasheet: http://www.ti.com/lit/ds/symlink/tps7a02.pdf; PART_TYPE: VOLTAGE\REGULATOR; ROHS: Yes; STATUS: Production
U15 = TPS22976: IC LOADSWITCH LOW IQ 2-CH 0.6-5.7V 6A WSON-14; AMBIQ_PN: AM-07-2349; DISTRIBUTOR: MOUSER; DISTRIBUTOR_PN: 595-TPS22976DPUR; HEIGHT: 0.8MM; IC Type: WSON-14; LEAD_FREE: Yes; MFG_NAME: TEXAS INSTRUMENTS; Manufacturer_Datasheet: https://www.ti.com/lit/ds/symlink/tps22976.pdf?ts=1602548409947&ref_url=https%253A%252F%252Fwww.ti.com%252Fpower-management%252Fpower-switches%252Fload-switches%252Fproducts.html; PART_TYPE: SWITCH; ROHS: Yes; STATUS: Production
U16 = TPS22919: IC LOADSWITCH LOW IQ 1.6-5.5V 1.5A SC-70; AMBIQ_PN: AM-07-2348; DISTRIBUTOR: MOUSER; DISTRIBUTOR_PN: 595-TPS22919DCKR; HEIGHT: 1.1mm; IC Type: SC70; LEAD_FREE: Yes; MFG_NAME: TEXAS INSTRUMENTS; Manufacturer_Datasheet: https://www.ti.com/lit/ds/symlink/tps22919.pdf?ts=1599257340346&ref_url=https%253A%252F%252Fwww.ti.com%252Fpower-management%252Fpower-switches%252Fload-switches%252Fproducts.html; PART_TYPE: SWITCH; ROHS: Yes; STATUS: Production
C36 = CAP_NP: CAP CER 0.1uF 16V 10% X7R 0402; AMBIQ_PN: AM-02-1045; DISTRIBUTOR: DIGIKEY; DISTRIBUTOR_PN: 587-1451-1-ND; Dielectric Material: X7R; HEIGHT: 0.55MM; LEAD_FREE: Yes; MFG_NAME: TAIYO YUDEN; MFG_PN: EMK105B7104KV-F; Manufacturer_Datasheet: http://www.yuden.co.jp/or/product/category/capacitor/EMK105B7104KV-F.pdf; PART_TYPE: CER\0402; Package Size: 0402; Package Type: SMD; ROHS: Yes; STATUS: Production; TOL: 10%; VOLTAGE: 16V
C37 = CAP_NP: CAP CER 1uF 16V 10% X5R 0402; AMBIQ_PN: AM-02-1077; DISTRIBUTOR: MOUSER; DISTRIBUTOR_PN: 963-EMK105BJ105KV-F; Dielectric Material: X5R; HEIGHT: 0.55MM; LEAD_FREE: Yes; MFG_NAME: TAIYO YUDEN; MFG_PN: EMK105BJ105KV-F; Manufacturer_Datasheet: http://ds.yuden.co.jp/TYCOMPAS/ut/detail.do?productNo=EMK105BJ105KV-F&fileName=EMK105BJ105KV-F_SS&mode=specSheetDownload; PART_TYPE: CER\0402; Package Size: 0402; Package Type: SMD; ROHS: Yes; STATUS: Production; TOL: 10%; VOLTAGE: 16V
C38 = CAP_NP: CAP CER 4.7UF 10V 10% X5R 0402; AMBIQ_PN: AM-02-1107; DISTRIBUTOR: DIGIKEY; DISTRIBUTOR_PN: 490-13252-1-ND; Dielectric Material: X5R; HEIGHT: 0.80MM; LEAD_FREE: Yes; MFG_NAME: MURATA; MFG_PN: ZRB15XR61A475KE01D; Manufacturer_Datasheet: https://www.digikey.com/product-detail/en/murata-electronics-north-america/ZRB15XR61A475KE01D/490-13252-1-ND/5877460; PART_TYPE: CER\0402; Package Size: 0402; Package Type: SMD; ROHS: Yes; STATUS: Production; TOL: 10%; VOLTAGE: 10V
J4 J6 = 1054500101: CONN RCP USB3.1 TYPEC 24P SMD RA; AMBIQ_PN: AM-03-1289; DISTRIBUTOR: DIGIKEY; DISTRIBUTOR_PN: WM12856CT-ND; HEIGHT: 3.24MM; LEAD_FREE: Yes; MFG_NAME: MOLEX; Manufacturer_Datasheet: https://www.molex.com/pdm_docs/sd/1054500101_sd.pdf; PART_TYPE: USB; Package Size: 8.64X7.31MM; Package Type: SMD; ROHS: Yes; STATUS: Production
J5 = CONN_HDR_3X1: HDR 1x3 SMD 100MIL; AMBIQ_PN: AM-03-1295; DISTRIBUTOR: DIGIKEY; DISTRIBUTOR_PN: SAM8981-ND; HEIGHT: 9.65MM; LEAD_FREE: Yes; MFG_NAME: SAMTEC; MFG_PN: TSM-103-01-L-SV; Manufacturer_Datasheet: http://suddendocs.samtec.com/catalog_english/tsm.pdf; PART_TYPE: HEADER; Package Type: SMD; ROHS: Yes; STATUS: Production
L3 L4 = INDUCTOR_FERRITE: IND FER BEAD 80 OHM @100MHZ DCR < 0.01 4A 1206; AMBIQ_PN: AM-08-0395; DISTRIBUTOR: DIGIKEY; DISTRIBUTOR_PN: 587-1772-1-ND; HEIGHT: 1.3MM; Inductance (Nominal) (H): 80OHM; LEAD_FREE: Yes; MFG_NAME: TAIYO YUDEN; MFG_PN: FBMJ3216HS800-T; Manufacturer_Datasheet: http://www.yuden.co.jp/ut/product/category/emisuppression/FBMJ3216HS800-T.pdf; PART_TYPE: FERRITE\BEAD; Package Size: 1206; ROHS: Yes; Rated Current: 4A; STATUS: Production
R16 R17 R22 R23 = RES: RES MF 5.1K 1/16W 1% 0402; AMBIQ_PN: AM-01-2072; HEIGHT: 0.4MM; LEAD_FREE: Yes; MFG_NAME: THYE MING TECH CO LTD; MFG_PN: CR02FL6--5K1; Manufacturer_Datasheet: http://www.tmtec.com.tw/tmtec/document/CR_series/CR02_1_datasheet_v1.pdf; PART_TYPE: 0402; Power Rating (Max) (W): 1/16W; ROHS: Yes; STATUS: Production; TOL: 1%
R18 = RES: RES MF 4.70K 1/16W 1% 0402; AMBIQ_PN: AM-01-1838; ASSY_OPT: DNP; HEIGHT: 0.4mm; LEAD_FREE: Yes; MFG_NAME: KOA SPEER; MFG_PN: RK73H1ETTP4701F; Manufacturer_Datasheet: http://www.koaspeer.com/pdfs/res5.pdf; PART_TYPE: 0402; PCB_FOOTPRINT_OPTIONS: RC0402_25,RC0402_HD,RC0402_CC; PEAK_REFLOW_TEMP: 260; ROHS: Yes; STATUS: Production; TOL: 1%
R19 = RES: RES MF 10K 1/16W 5% 0402; AMBIQ_PN: AM-01-0463; HEIGHT: 0.4 MM; LEAD_FREE: Yes; MFG_NAME: SEI ELECTRONICS INC; MFG_PN: RMCF1/16S10K5%R; Manufacturer_Datasheet: http://www.seielect.com/catalog/sei-rmc.pdf; PART_TYPE: 0402; Power Rating (Max) (W): 0.0625W; ROHS: Yes; STATUS: Production; TOL: 5%; Type: SMD
R20 = RES: RES MF 44.2K  1/16W 1% 0402; AMBIQ_PN: AM-01-1920; HEIGHT: 0.40 MM; LEAD_FREE: Yes; MFG_NAME: KOA SPEER; MFG_PN: RK73H1ETTP4422F; Manufacturer_Datasheet: http://www.koaspeer.com/pdfs/res5.pdf; PART_TYPE: 0402; Power Rating (Max) (W): 0.1W; ROHS: Yes; STATUS: Production; TOL: 1%
R49 = RES: RES MF 2.2K 1/16W 5% 0402; AMBIQ_PN: AM-01-0923; HEIGHT: 0.4 MM; LEAD_FREE: Yes; MFG_NAME: VENKEL COMPANY; MFG_PN: CR0402-16W-222JT; Manufacturer_Datasheet: http://www.venkel.com/FinalPDFs/PID_CR.pdf; PART_TYPE: 0402; Power Rating (Max) (W): 1/16W; ROHS: Yes; STATUS: Production; TOL: 5%; Type: SMD
SH1 = Shunt: SHUNT 0.1IN SP BLUE AU; AMBIQ_PN: AM-09-0255; HEIGHT: 6.1MM; LEAD_FREE: Yes; MFG_NAME: SAMTEC; Manufacturer_Datasheet: http://www.samtec.com/ftppub/pdf/SNT.PDF; PART_TYPE: JUMPER; ROHS: Yes; STATUS: Production
SW4 = JS202011SCQN: SW SLIDE DPDT SMT 300MA 6V; AMBIQ_PN: AM-09-0335; DISTRIBUTOR: DIGIKEY; HEIGHT: 5.5MM; LEAD_FREE: Yes; MFG_NAME: C&K COMPONENTS; Manufacturer_Datasheet: https://dznh3ojzb2azq.cloudfront.net/products/Slide/JS/documents/datasheet.pdf; PART_TYPE: SWITCHES\SLIDE/SM; STATUS: Production
U6 U8 = PRTR5V0U2X: IC USB ESD PROTECTION 8KV SOT143; AMBIQ_PN: AM-07-1700; HEIGHT: 1.1MM; LEAD_FREE: Yes; MFG_NAME: PHILIPS SEMICONDUCTOR; Manufacturer_Datasheet: http://www.nxp.com/acrobat_download/datasheets/PRTR5V0U2X_1.pdf; PART_TYPE: USB_DEVICE; ROHS: Yes; STATUS: Production
U7 = NCP380LMUAJAATBG: IC CURRENT LIMIT SWITCH 0.100-2.1A 2.5-5.5V UDFN6; AMBIQ_PN: AM-07-2216; DISTRIBUTOR: DIGIKEY; DISTRIBUTOR_PN: NCP380LMUAJAATBGOSCT-ND; HEIGHT: 0.55MM; IC Type: CURRENT LIMIT SWITCH; LEAD_FREE: Yes; MFG_NAME: ON SEMICONDUCTOR; Manufacturer_Datasheet: http://www.onsemi.com/pub_link/Collateral/NCP380-D.PDF; PART_TYPE: LINEAR\SWITCH; ROHS: Yes; STATUS: Production
C80-C92 C94 C95 = CAP_NP: CAP CER 0.1UF 10V 10% X5R 0201; AMBIQ_PN: AM-02-1050; DISTRIBUTOR: DIGIKEY; DISTRIBUTOR_PN: 587-2241-1-ND; Dielectric Material: X5R; HEIGHT: 0.33MM; LEAD_FREE: Yes; MFG_NAME: TAIYO YUDEN; MFG_PN: LMK063BJ104KP-F; Manufacturer_Datasheet: http://www.yuden.co.jp/or/product/category/capacitor/LMK063BJ104KP-F.pdf; PART_TYPE: CER\0201; PCB_FOOTPRINT_OPTIONS: CC0402_25,CC0402_HD,CC0402_CC; PEAK_REFLOW_TEMP: 260; Package Size: 0201; Package Type: SMD; ROHS: Yes; STATUS: Production; TOL: 10%; VOLTAGE: 10V
C93 = CAP_NP: CAP CER 0.1UF 10V 10% X5R 0201; AMBIQ_PN: AM-02-1050; ASSY_OPT: DNP; DISTRIBUTOR: DIGIKEY; DISTRIBUTOR_PN: 587-2241-1-ND; Dielectric Material: X5R; HEIGHT: 0.33MM; LEAD_FREE: Yes; MFG_NAME: TAIYO YUDEN; MFG_PN: LMK063BJ104KP-F; Manufacturer_Datasheet: http://www.yuden.co.jp/or/product/category/capacitor/LMK063BJ104KP-F.pdf; PART_TYPE: CER\0201; PCB_FOOTPRINT_OPTIONS: CC0402_25,CC0402_HD,CC0402_CC; PEAK_REFLOW_TEMP: 260; Package Size: 0201; Package Type: SMD; ROHS: Yes; STATUS: Production; TOL: 10%; VOLTAGE: 10V
R71 = RES: RES MF 10K 1/16W 5% 0402; AMBIQ_PN: AM-01-0463; ASSY_OPT: DNP; HEIGHT: 0.4 MM; LEAD_FREE: Yes; MFG_NAME: SEI ELECTRONICS INC; MFG_PN: RMCF1/16S10K5%R; Manufacturer_Datasheet: http://www.seielect.com/catalog/sei-rmc.pdf; PART_TYPE: 0402; Power Rating (Max) (W): 0.0625W; ROHS: Yes; STATUS: Production; TOL: 5%; Type: SMD
SB85 = SB_Open: Solder-Bridge, No Connect, 39X18 PAD; AMBIQ_PN: AM-03-1290; PART_TYPE: MISC; ROHS: Yes; STATUS: Production
U18-U21 = NLSX5012MUTAG: IC TRNSLTR BIDIRECTIONAL 8UDFN; AMBIQ_PN: AM-07-2363; DISTRIBUTOR: DIGIKEY; DISTRIBUTOR_PN: NLSX5012MUTAGOSTR-ND; HEIGHT: 0.5mm; IC Type: LEVEL SHIFTER; LEAD_FREE: Yes; MFG_NAME: ON SEMICONDUCTOR; Manufacturer_Datasheet: https://www.onsemi.com/pdf/datasheet/nlsx5012-d.pdf; PART_TYPE: LEVEL SHIFTER; ROHS: Yes; STATUS: Production
U22 = MK22FN128VLH10: IC 32-Bit 100MHz 128KB (128K x 8) FLASH 64-LQFP (10x10); AMBIQ_PN: AM-07-2362; HEIGHT: 1.4mm; IC Type: MCU; LEAD_FREE: Yes; MFG_NAME: NXP; Manufacturer_Datasheet: https://www.nxp.com/docs/en/data-sheet/K22P121M100SF9.pdf; PART_TYPE: MCU; ROHS: Yes; STATUS: Production
J7 J9 = CONN_HDR_8X1: HDR 1x8 SMD 100MIL Female; AMBIQ_PN: AM-03-1298; DISTRIBUTOR: DIGIKEY; DISTRIBUTOR_PN: SAM14607TR-ND; HEIGHT: 7.37MM; LEAD_FREE: Yes; MFG_NAME: SAMTEC; Manufacturer_Datasheet: http://suddendocs.samtec.com/catalog_english/ssm_sm.pdf; PART_TYPE: HEADER; Package Type: SMD; ROHS: Yes; STATUS: Production
J8 = QSH030: CON 2X30 SKT SMT 0.5MM SP 120H AU; AMBIQ_PN: AM-03-0924; Contact Plating: Au; FPLIST: CON_60S_QSH_SM,CON_60S_QSH_SM_A; HEIGHT: 3.25 MM; LEAD_FREE: Yes; MFG_NAME: SAMTEC; Manufacturer_Datasheet: http://www.samtec.com/ftppub/pdf/QSH.PDF; Number Of Contact Rows: 2; Number Of Contacts: 30X2; PART_TYPE: RECEPTACLE\OTHER; PCB Contact Spacing: 0.5mm SP; PEAK_REFLOW_TEMP: 260; Package Size: SMD-60; Package Type: SMD; ROHS: Yes; STATUS: Production; Type: SKT
J10 J11 = CONN_HDR_8X2: HDR 2x8 SMD 100MIL Female; AMBIQ_PN: AM-03-1296; DISTRIBUTOR: DIGIKEY; DISTRIBUTOR_PN: SAM14603TR-ND; HEIGHT: 7.37MM; LEAD_FREE: Yes; MFG_NAME: SAMTEC; Manufacturer_Datasheet: http://suddendocs.samtec.com/catalog_english/ssm_sm.pdf; PART_TYPE: HEADER; Package Type: SMD; ROHS: Yes; STATUS: Production
J12 = CONN_HDR_10X2: HDR 2x10 SMD 100MIL Female; AMBIQ_PN: AM-03-1297; DISTRIBUTOR: DIGIKEY; DISTRIBUTOR_PN: SAM14612TR-ND; HEIGHT: 7.37MM; LEAD_FREE: Yes; MFG_NAME: SAMTEC; Manufacturer_Datasheet: http://suddendocs.samtec.com/catalog_english/ssm_sm.pdf; PART_TYPE: HEADER; Package Type: SMD; ROHS: Yes; STATUS: Production
R32 R33 = RES: RES TF 100 OHM 1/20W 1% 0201; AMBIQ_PN: AM-01-2949; ASSY_OPT: DNP; DISTRIBUTOR: MOUSER; DISTRIBUTOR_PN: 71-CRCW0201100RFNED; HEIGHT: 0.26 MM; LEAD_FREE: Yes; MFG_NAME: VISHAY DALE; MFG_PN: CRCW0201100RFNED; Manufacturer_Datasheet: http://www.vishay.com/docs/20052/crcw0201e3.pdf; PART_TYPE: 0201; Power Rating (Max) (W): 1/20W; ROHS: Yes; STATUS: Production; TOL: 1%; Type: SMD
J19-J24 = CONN_HDR_8X1: 1.5MM TH Testpoint Array 100mil 1X8; AMBIQ_PN: AM-09-0337; ASSY_OPT: DNP; PART_TYPE: MISC; ROHS: Yes; STATUS: Production
J25 J26 = CONN_HDR_10X1: 1.5MM TH Testpoint Array 100mil 1X10; AMBIQ_PN: AM-09-0338; ASSY_OPT: DNP; PART_TYPE: MISC; ROHS: Yes; STATUS: Production

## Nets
GND: C28.1 C29.1 C30.2 C31.2 C32.2 C33.2 C34.2 C35.2 C36.1 C37.1 C38.1 C72.2 C73.2 C74.2 C75.2 C76.1 C77.1 C78.1 C79.2 C80.1 C81.1 C82.1 C83.1 C84.1 C85.1 C86.1 C87.1 C88.1 C89.1 C90.1 C91.1 C92.1 C93.1 C94.1 C95.1 D8.1(CATHODE) J2.7(A4) J2.9(A5) J3.7(A4) J3.8(B4) J4.A1(GND) J4.A12(GND) J4.B1(GND) J4.B12(GND) J4.SH1 J4.SH2 J4.SH3 J4.SH4 J6.A1(GND) J6.A12(GND) J6.B1(GND) J6.B12(GND) J6.SH1 J6.SH2 J6.SH3 J6.SH4 J7.6 J7.7 J8.9 J8.10 J8.15 J8.16 J8.21 J8.57 J8.SH1 J8.SH2 J8.SH3 J8.SH4 J12.13(A7) J12.16(B8) J12.20(B10) J19.6 J19.7 J25.7 J26.8 J26.10 R13.2 R14.2 R15.2 R16.2 R17.2 R18.2 R20.2 R22.2 R23.2 R51.2 R54.2 R57.2 SB15.2 SW4.3(NO2) SW4.6(NO1) TP5.1(Pin1) TP6.1(Pin1) TP7.1(Pin1) U2.2(GND) U2.7(TPAD) U3.2(GND) U3.7(TPAD) U4.2(GND) U4.7(TPAD) U5.2(GND) U5.5(PAD) U6.1(GND) U7.5(GND) U7.7(PAD) U8.1(GND) U15.11(GND) U15.15(PAD) U16.2(GND) U18.4(GND) U19.4(GND) U20.4(GND) U21.4(GND) U22.4(VSS1) U22.15(VREFL) U22.16(VSSA) U22.31(VSS2) U22.32(PTA18) U22.47(VSS3) ; also on sheet 7 8 9 10
VBUS_5V: C36.2 C37.2 J5.2 R18.1 R19.2 U7.6(IN)
VBUS_AP4: J5.1 L3.2
VBUS_JLINK: J5.3 L4.2
VDD18: J2.10(B5) R55.2 SB9.1 ; also on sheet 9
VDD18EN_GP14: R56.2 R57.1 SB61.1 U16.3(ON)
VDD18LN_TPS: C34.1 SB16.1 U5.1(OUT)
VDD_0.9V: C33.1 C75.1 R11.1 TP4.1(Pin1) U4.4(VOUT) U15.6(VIN2_1) U15.7(VIN2_2)
VDD_1.8V: C31.1 C79.1 J3.1(A1) R9.1 SB3.1 SB4.2 SB84.1 TP2.1(Pin1) U2.4(VOUT) U16.1(IN)
VDD_3.3V: C30.1 C32.1 C35.1 C74.1 J3.5(A3) R10.1 SB75.1 TP3.1(Pin1) U3.4(VOUT) U4.1(EN) U4.6(VIN) U5.3(EN) U5.4(IN) U15.1(VIN1) U15.2(VIN1)
VDD_5V: C28.2 C29.2 C38.2 C78.2 J3.6(B3) J7.5 J8.6 J8.8 J19.5 R49.1 SB17.2 U2.1(EN) U2.6(VIN) U3.1(EN) U3.6(VIN) U15.4(VBIAS) ; also on sheet 7 8
VDD_EXT: J3.3(A2) J7.2 J7.4 J19.2 J19.4 SB5.1 SB85.1 ; also on sheet 8
VDD_MCU_TRACK: R52.1 R53.1 R56.1 R62.2 R63.1 R64.2 R65.1 R66.2 R67.1 ; also on sheet 7
VDDA: J2.1(A1) J3.2(B1) J3.4(B2) J7.1 J8.2 J8.4 J12.15(A8) J19.1 J25.8 SB3.2 SB5.2 SB6.1 SB7.1 SB8.1 ; also on sheet 7 9
VDDAUDA: J2.8(B4) SB15.1 SB16.2 ; also on sheet 8 9
VDDAUDD: J2.6(B3) SB8.2 ; also on sheet 9
VDDB: J2.2(B1) SB7.2 ; also on sheet 9
VDDH2: J2.3(A2) J7.8 J19.8 SB6.2 ; also on sheet 9
VDDUSB0P9: C77.2 J2.4(B2) SB11.2 ; also on sheet 9
VDDUSB0P9EN_GP15: R51.1 R52.2 SB60.1 U15.5(ON2)
VDDUSB33: C76.2 J2.5(A3) SB13.2 ; also on sheet 9
VDDUSB33EN_GP13: R53.2 R54.1 SB59.1 U15.3(ON1)
ADC0_CTS23_I2S1DIN_GP19: J9.1 J20.1 ; also on sheet 9
ADC1_I2S1WS_CTS01_GP18: J9.2 J20.2 ; also on sheet 9
ADC2_I2S1DAT_RTS3_I2S1DOUT_GP17: J9.3 J20.3 ; also on sheet 9
ADC3_I2S1CK_RTS1_GP16: J9.4 J20.4 ; also on sheet 9
ADC4_RX3_REFCLK_GP15: J9.5 J20.5 SB60.2 ; also on sheet 9
ADC5_RX1_I2S0DIN_GP14: J9.6 J20.6 SB61.2 ; also on sheet 9
ADC6_I2S0WS_TX23_GP13: J9.7 J20.7 SB59.2 ; also on sheet 9
ADC7_I2S0DAT_TX01_CMRF2_I2S0DOUT_GP12: J9.8 J20.8 ; also on sheet 9
AP4_USBN: J4.A7(DN1) J4.B7(DN2) U6.2(I/O1) ; also on sheet 9
AP4_USBP: J4.A6(DP1) J4.B6(DP2) U6.3(I/O2) ; also on sheet 9
AT_3.3V: C80.2 C81.2 C82.2 C83.2 C84.2 C85.2 C87.2 C89.2 C91.2 C94.2 C95.2 R34.2 R35.2 R36.2 R71.2 R72.2 R74.2 R75.2 R76.2 SB75.2 U18.1(VL) U19.1(VL) U20.1(VL) U21.1(VL) U22.3(VDD1) U22.7(USBVDD) U22.13(VDDA) U22.14(VREFH) U22.21(VBAT) U22.26(PTA4/LLWU_P3) U22.30(VDD2) U22.48(VDD3) ; also on sheet 10
AT_PTB2_RTS: U20.3(I/O_VL2) U22.37(PTB2)
AT_PTB3_CTS: U20.2(I/O_VL1) U22.38(PTB3)
AT_PTB16_RXD: U21.3(I/O_VL2) U22.39(PTB16)
AT_PTB17_TXD: U21.2(I/O_VL1) U22.40(PTB17)
AT_PTD5_SWCLK: U18.3(I/O_VL2) U22.62(PTD5)
AT_PTD6_SWDIO: U18.2(I/O_VL1) U22.63(PTD6/LLWU_P15)
AT_PTD7_SWRST: U19.3(I/O_VL2) U22.64(PTD7)
AT_PTE1_SWO: U19.2(I/O_VL1) U22.2(PTE1/LLWU_P0)
AT_SWO: SB77.2 ; also on sheet 10
AT_SWRST: J7.3 J19.3 SB76.2 ; also on sheet 9 10
AT_USBN: J6.A7(DN1) J6.B7(DN2) R78.2 U8.2(I/O1)
AT_USBP: J6.A6(DP1) J6.B6(DP2) R77.2 U8.3(I/O2)
AT_VDDIO: C86.2 C88.2 C90.2 C92.2 SB84.2 SB85.2 U18.8(VCC) U19.8(VCC) U20.8(VCC) U21.8(VCC)
CMIN0_M1MISO_TE_GP10: J11.5(A3) J23.3 ; also on sheet 9
CMIN1_I2S0CK_RX23_GP11: J11.7(A4) J23.4 ; also on sheet 9
CMRF0_M1SDA_M1MOSI_GP9: J11.1(A1) J23.1 ; also on sheet 9
CMRF1_M1SCL_M1SCK_GP8: J11.3(A2) J23.2 ; also on sheet 9
CTS01_GP59: J10.14(B7) J22.7 SB83.2 ; also on sheet 9
DISPCM_GP89: J8.48 ; also on sheet 9
HDR_MSPI00_32KXT_RTS0_DISPD0_I2S1DIN_GP64: J12.14(B7) J26.7 SB56.2
HDR_MSPI01_32KXT_CTS0_DISPD1_GP65: J12.12(B6) J26.6 SB55.2
HDR_MSPI02_CKO_TX0_DISPD2_GP66: J12.10(B5) J26.5 SB30.2
HDR_MSPI03_CKO_TX2_DISPD3_GP67: J12.8(B4) J26.4 SB31.2
HDR_MSPI04_SWO_RX0_DISPD4_GP68: J12.6(B3) J26.3 SB32.2
HDR_MSPI05_32KXT_SWO_RX2_DISPD5_GP69: J12.4(B2) J26.2 SB33.2
HDR_MSPI06_32KXT_SWTR0_RTS0_DISPD6_GP70: J12.2(B1) J26.1 SB34.2
HDR_MSPI07_CKO_SWTR1_CTS0_DISPD7_GP71: J11.16(B8) J24.8 SB35.2
HDR_MSPI08_CKO_SWTR2_TX0_DISPD8_GP72: J11.14(B7) J24.7 SB53.2
HDR_MSPI09_SWTR3_TX2_DISPD9_GP73: J11.12(B6) J24.6 SB54.2
HDR_MSPI10_32KXT_RX2_DISPD15_GP37: J10.10(B5) J22.5 SB36.2
HDR_PDM0CK_SWTRCK_RTS23_TE_GP50: J10.4(B2) J22.2 SB42.1
HDR_PDM0DAT_SWTR0_CTS01_GP51: J10.5(A3) J21.3 SB43.1
HDR_PDM1CK_SWTR1_CTS23_VCO_GP52: J11.13(A7) J23.7 SB44.1
HDR_PDM1DAT_SWTR2_TX01_GP53: J11.15(A8) J23.8 SB45.1
HDR_PDM2CK_SWTR3_TX23_GP54: J10.8(B4) J22.4 SB46.1
HDR_PDM2DAT_SWTRCTL_RX01_GP55: J10.9(A5) J21.5 SB57.1
HDR_SWO_VCO_IS20CK_DSPTDO_GP28: J10.15(A8) J21.8 SB58.1
JLINK_nRST: C93.2 R71.1 U22.34(\\~{RESE}T) ; also on sheet 10
JLINK_SWCLK: U22.22(PTA0) ; also on sheet 10
JLINK_SWDIO: U22.25(PTA3) ; also on sheet 10
JLINK_SWO: U22.24(PTA2) ; also on sheet 10
M0MISO_I2S0WS_CTS23_GP7: J8.24 ; also on sheet 9
M0SCL_M0SCK_I2S0CK_RTS23_GP5: J8.26 ; also on sheet 9
M0SDA_M0MOSI_I2S0DAT_CTS01_I2S0DOUT_GP6: J8.28 ; also on sheet 9
M2MISO_DSPTCK_I2S0DIN_GP27: J8.50 ; also on sheet 9
M2SCL_M2SCK_DSPTMS_GP25: J8.58 ; also on sheet 9
M2SDA_M2MOSI_DSPTCK_GP26: J8.60 ; also on sheet 9
M3MISO_CKO_RX2_TE_GP33: J11.6(B3) J24.3 ; also on sheet 9
M3SCL_M3SCK_TX2_GP31: J11.2(B1) J24.1 ; also on sheet 9
M3SDA_M3MOSI_RX0_GP32: J11.4(B2) J24.2 ; also on sheet 9
M5MISO_I2S1WS_RTS01_GP49: J12.3(A2) J25.2 ; also on sheet 9
M5SCL_M5SCK_I2S1CK_RX01_GP47: J12.5(A3) J25.3 SB80.2 ; also on sheet 9
M5SDA_M5MOSI_I2S1DAT_RX23_I2S1DOUT_GP48: J12.1(A1) J25.1 ; also on sheet 9
M6MISO_CKO_I2S1WS_RX23_TE_GP63: J12.9(A5) J25.5 ; also on sheet 9
M6SCL_M6SCK_I2S1CK_TX23_GP61: J12.11(A6) J25.6 ; also on sheet 9
M6SDA_M6MOSI_I2S1DAT_RX01_I2S1DOUT_GP62: J12.7(A4) J25.4 ; also on sheet 9
M7MISO_SWO_RTS01_GP24: J12.18(B9) J26.9 ; also on sheet 9
M7SCL_M7SCK_SWO_RX01_GP22: J12.19(A10) J25.10 ; also on sheet 9
M7SDA_M7MOSI_SWO_RX23_GP23: J12.17(A9) J25.9 ; also on sheet 9
MIPI_CLKN: J8.13 R32.1 ; also on sheet 9
MIPI_CLKP: J8.11 R32.2 ; also on sheet 9
MIPI_D0N: J8.19 R33.1 ; also on sheet 9
MIPI_D0P: J8.17 R33.2 ; also on sheet 9
MSPI00_32KXT_RTS0_DISPD0_I2S1DIN_GP64: J8.29 SB56.1 ; also on sheet 9
MSPI01_32KXT_CTS0_DISPD1_GP65: J8.31 SB55.1 ; also on sheet 9
MSPI02_CKO_TX0_DISPD2_GP66: J8.33 SB30.1 ; also on sheet 9
MSPI03_CKO_TX2_DISPD3_GP67: J8.34 SB31.1 ; also on sheet 9
MSPI04_SWO_RX0_DISPD4_GP68: J8.35 SB32.1 ; also on sheet 9
MSPI05_32KXT_SWO_RX2_DISPD5_GP69: J8.36 SB33.1 ; also on sheet 9
MSPI06_32KXT_SWTR0_RTS0_DISPD6_GP70: J8.37 SB34.1 ; also on sheet 9
MSPI07_CKO_SWTR1_CTS0_DISPD7_GP71: J8.38 SB35.1 ; also on sheet 9
MSPI08_CKO_SWTR2_TX0_DISPD8_GP72: J8.25 SB53.1 ; also on sheet 9
MSPI09_SWTR3_TX2_DISPD9_GP73: J8.27 SB54.1 ; also on sheet 9
MSPI10_32KXT_RX2_DISPD15_GP37: J8.56 SB36.1 ; also on sheet 9
MSPI11_SWTRCK_RTS0_DISPD16_GP38: J10.11(A6) J21.6 ; also on sheet 9
MSPI20_QSPID0_RX0_DISPD10_DSPISD_GP74: J8.53 ; also on sheet 9
MSPI21_QSPID1_RX2_DISPD11_DSPIDCX_GP75: J8.51 ; also on sheet 9
MSPI22_QSPID2_RTS0_DISPD12_GP76: J8.49 ; also on sheet 9
MSPI23_QSPID3_CTS0_DISPD13_GP77: J8.47 ; also on sheet 9
MSPI24_QSPISCK_DISPD14_DSPISCK_GP78: J8.45 ; also on sheet 9
MSPI25_SDIFD4_SWO_DISPVS_GP79: J8.43 ; also on sheet 9
MSPI26_CKO_SDIFD5_SWTR0_DISPHS_GP80: J8.41 ; also on sheet 9
MSPI27_CKO_SDIFD6_SWTR1_DISPDE_GP81: J8.39 ; also on sheet 9
MSPI28_32KXT_SDIFD7_SWTR2_DISPPCK_GP82: J8.59 ; also on sheet 9
MSPI29_32KXT_SDIFCMD_SWTR3_DISPSD_GP83: J8.55 ; also on sheet 9
PDM0CK_SWTRCK_RTS23_TE_GP50: SB42.2 ; also on sheet 9 10
PDM0DAT_SWTR0_CTS01_GP51: SB43.2 ; also on sheet 9 10
PDM1CK_SWTR1_CTS23_VCO_GP52: SB44.2 ; also on sheet 9 10
PDM1DAT_SWTR2_TX01_GP53: SB45.2 ; also on sheet 9 10
PDM2CK_SWTR3_TX23_GP54: SB46.2 ; also on sheet 9 10
PDM2DAT_SWTRCTL_RX01_GP55: SB57.2 ; also on sheet 9 10
PDM3CK_SWO_RX23_GP56: J8.30 ; also on sheet 9
PDM3DAT_SWO_RTS01_VCO_GP57: J8.32 ; also on sheet 9
RTS03_GP58: J10.12(B6) J22.6 SB82.2 ; also on sheet 9
SDIFCK0_GP88: J8.46 ; also on sheet 9
SDIFD0_GP84: J8.40 ; also on sheet 9
SDIFD1_GP85: J8.42 ; also on sheet 9
SDIFD2_GP86: J8.44 ; also on sheet 9
SDIFD3_TE_GP87: J8.52 ; also on sheet 9
SWDCK_TX01_GP20: SB78.2 ; also on sheet 9 10
SWDIO_TX23_GP21: SB79.2 ; also on sheet 9 10
SWO_VCO_IS20CK_DSPTDO_GP28: SB58.2 ; also on sheet 9 10
TRC0_SSDA_SMOSI_TX23_VCO_GP1: J10.6(B3) J22.3 ; also on sheet 9
TRC1_SMISO_TRIG1_RX01_VCO_GP2: J10.3(A2) J21.2 ; also on sheet 9
TRC2_SCEn_SWO_RX23_GP3: J10.1(A1) J21.1 ; also on sheet 9
TRC3_SINT_32KXT_RTS01_I2S0DIN_GP4: J10.2(B1) J22.1 ; also on sheet 9
TRCLK_SSCL_SSCK_TX01_VCO_GP0: J10.7(A4) J21.4 ; also on sheet 9
TRIG0_VCO_I2S0DAT_CTS1_DSPTRSTN_I2S0DOUT_GP29: J8.54 ; also on sheet 9
TRIG1_VCO_I2S0WS_TX0_DSPTDI_GP30: J10.13(A7) J21.7 SB37.2 ; also on sheet 9
TX0_CTS3_GP60: J10.16(B8) J22.8 SB81.2 ; also on sheet 9
TXEN: J11.8(B4) J24.4 ; also on sheet 9
USB0_DN: R78.1 U22.6(USB0_DM)
USB0_DP: R77.1 U22.5(USB0_DP)
VCO_GP90: J11.9(A5) J23.5 SB38.2 ; also on sheet 9
VCO_GP91: J11.11(A6) J23.6 SB39.2 ; also on sheet 9
N548016: R10.2 R13.1 U3.5(ADJ)
N548084: R9.2 R12.2 R15.1 U2.5(ADJ)
N548520: R11.2 R14.1 U4.5(ADJ)
N553022: J4.A4(VBUS) J4.A9(VBUS) J4.B4(VBUS) J4.B9(VBUS) L3.1 U6.4(VCC)
N553538: J4.B5(CC2) R16.1
N553542: J4.A5(CC1) R17.1
N554596: J6.A4(VBUS) J6.A9(VBUS) J6.B4(VBUS) J6.B9(VBUS) L4.1 U8.4(VCC)
N554738: J6.B5(CC2) R22.1
N554742: J6.A5(CC1) R23.1
N557437: R19.1 SW4.2(C2) SW4.5(C1) U7.4(~{EN})
N564582: R20.1 U7.2(ILIM)
N564875: SB17.1 U7.1(OUT)
N845171: D8.2(ANODE) R49.2
N1030581: SB13.1 U15.13(VOUT1_2) U15.14(VOUT1_1)
N1031371: C73.1 U15.10(CT2)
N1035993: R55.1 U16.5(QOD)
N1086467: SB11.1 U15.8(VOUT2_1) U15.9(VOUT2_2)
N1088722: SB9.2 U16.6(OUT)
N1090951: R12.1 SB4.1
N1091426: D4.2(ANODE) R35.1
N1091430: D5.2(ANODE) R36.1
N1091504: Q3.2(EMITTER) R63.2 SB37.1
N1091674: Q5.2(EMITTER) R67.2 SB39.1
N1091762: Q4.2(EMITTER) R65.2 SB38.1
N1107607: C72.1 U15.12(CT1)
N1122443: Q3.1(BASE) R62.1
N1122730: D3.1(CATHODE) Q3.3(COLLECTOR)
N1124472: Q4.1(BASE) R64.1
N1125056: D3.2(ANODE) R34.1
N1125341: D4.1(CATHODE) Q4.3(COLLECTOR)
N1125623: Q5.1(BASE) R66.1
N1125808: D5.1(CATHODE) Q5.3(COLLECTOR)
N1291235: SB76.1 U19.6(I/O_VCC2)
N1291247: SB77.1 U19.7(I/O_VCC1)
N1291275: SB79.1 U18.7(I/O_VCC1)
N1291287: SB78.1 U18.6(I/O_VCC2)
N1291529: R72.1 U21.5(EN)
N1291833: R74.1 U20.5(EN)
N1292323: R75.1 U19.5(EN)
N1292499: R76.1 U18.5(EN)
N1292653: SB81.1 U21.6(I/O_VCC2)
N1292665: SB80.1 U21.7(I/O_VCC1)
N1292829: SB82.1 U20.7(I/O_VCC1)
N1292841: SB83.1 U20.6(I/O_VCC2)

Not connected (* = marked no-connect by the designer): J4 A2(TX1+)* A3(TX1-)* A8(SBU1)* A10(RX2-)* A11(RX2+)* B2(TX2+)* B3(TX2-)* B8(SBU2)* B10(RX1-)* B11(RX1+)*; J6 A2(TX1+)* A3(TX1-)* A8(SBU1)* A10(RX2-)* A11(RX2+)* B2(TX2+)* B3(TX2-)* B8(SBU2)* B10(RX1-)* B11(RX1+)*; J8 1* 3* 5* 7* 12* 14* 18* 20* 22* 23*; J11 10(B5)*; J24 5*; SW4 1(NC2)* 4(NC1)*; U2 3(PG)*; U3 3(PG)*; U4 3(PG)*; U7 3(~{FLAG})*; U16 4(NC)*; U22 1(PTE0/CLKOUT32K)* 8(NC)* 9(ADC0_DP0/ADC1_DP3)* 10(ADC0_DM0/ADC1_DM3)* 11(ADC1_DP0/ADC0_DP3)* 12(ADC1_DM0/ADC0_DM3)* 17(VREF_OUT/CMP1_IN5/CMP0_IN5/ADC1_SE18)* 18(DAC0_OUT/CMP1_IN3/ADC0_SE23)* 19(XTAL32)* 20(EXTAL32)* 23(PTA1)* 27(PTA5)* 28(PTA12)* 29(PTA13/LLWU_P4)* 33(PTA19)* 35(PTB0/LLWU_P5)* 36(PTB1)* 41(PTB18)* 42(PTB19)* 43(PTC0)* 44(PTC1/LLWU_P6)* 45(PTC2)* 46(PTC3/LLWU_P7)* 49(PTC4/LLWU_P8)* 50(PTC5/LLWU_P9)* 51(PTC6/LLWU_P10)* 52(PTC7)* 53(PTC8)* 54(PTC9)* 55(PTC10)* 56(PTC11/LLWU_P11)* 57(PTD0/LLWU_P12)* 58(PTD1)* 59(PTD2/LLWU_P13)* 60(PTD3)* 61(PTD4/LLWU_P14)*

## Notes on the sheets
sheet 1
- 1.9V REGULATOR
- 1.9V Default. Connect SB51 for 1.8V
- 3.3V REGULATOR
- FALCON 0.9V USB SUPPLY
- 3.3V OUTPUT
- 1.8V LOW NOISE SUPPLY
- LED GPIO Solder-Bridges
- USB SEQUENCING
- MIPI SEQUENCING
- GND TEST LOOPS
sheet 2
- J-Link Onboard Debugger
- J-Link Voltage Disconnect Solder-Bridges
- OB JLINK DEBUG OUT
- TDO/SWO
- J-Link SWD Connections and Level Translation
- Matched Length
- ROUTE AT_USB_P AND
  AT_USB_N AS 90 OHM
  DIFFERENTIAL PAIR
- OB JLINK DEBUG IN
- VCOM0
- UART0_CTS
- UART0_RTS
- UART0_RX
- TDI
- OB JLINK DEBUG OUT
- J-Link To AP4 UART Solder-Bridges and Level Translation
- UART0_TX
- TCK/SWCLK
- TMS/SWDIO
- RESET
- RX/TX SWAP HERE
- RTS/CTS SWAP HERE
sheet 3
- AP4 USB Connector
- 5V Source Select & USB Protection Circuit
- J-Link USB Connector
sheet 4
- Arduino-Style GPIO Headers
- High-Speed Header
- Debug Signal to GPIO Connector Solder-Bridges
- Display Controller GPIO Solder-Bridges
- USB/MIPI Sequence Control
sheet 5
- J12 Testpoints
- J7 Testpoints
- J11 Testpoints
- J9 Testpoints
- J10 Testpoints
sheet 6
- 1/24/2022
- 1) Initial Release
